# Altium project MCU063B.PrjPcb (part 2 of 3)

## Sheet MCU063B_Power.SchDoc
size 431 x 279 mm; Date: Not shown in title block; ApprovedBy: Not shown in title block; CheckedBy: Not shown in title block; Author: Not shown in title block; CompanyName: Not shown in title block; DrawnBy: Cody Watkins; Engineer: Not shown in title block; Organization: Not shown in title block; Address1: Not shown in title block; Address2: Not shown in title block; Address3: Not shown in title block; Address4: Not shown in title block; DocumentNumber: 5; Revision: Use project parameter SCH_Rev; SheetNumber: 5; SheetTotal: 11; PageSetup: Record=PageOptions¦CenterHorizontal=True¦CenterVertical=True¦PrintScale=1.00¦XCorrection=1.00¦YCorrection=1.00¦PrintKind=0¦BorderSize=5000000¦LeftOffset=0¦BottomOffset=0¦Orientation=2¦PaperLength=1000¦PaperWidth=1000¦Scale=100¦PaperSource=15¦PrintQuality=600¦MediaType=1¦DitherType=10¦PaperKind=Letter¦PrintScaleMode=1
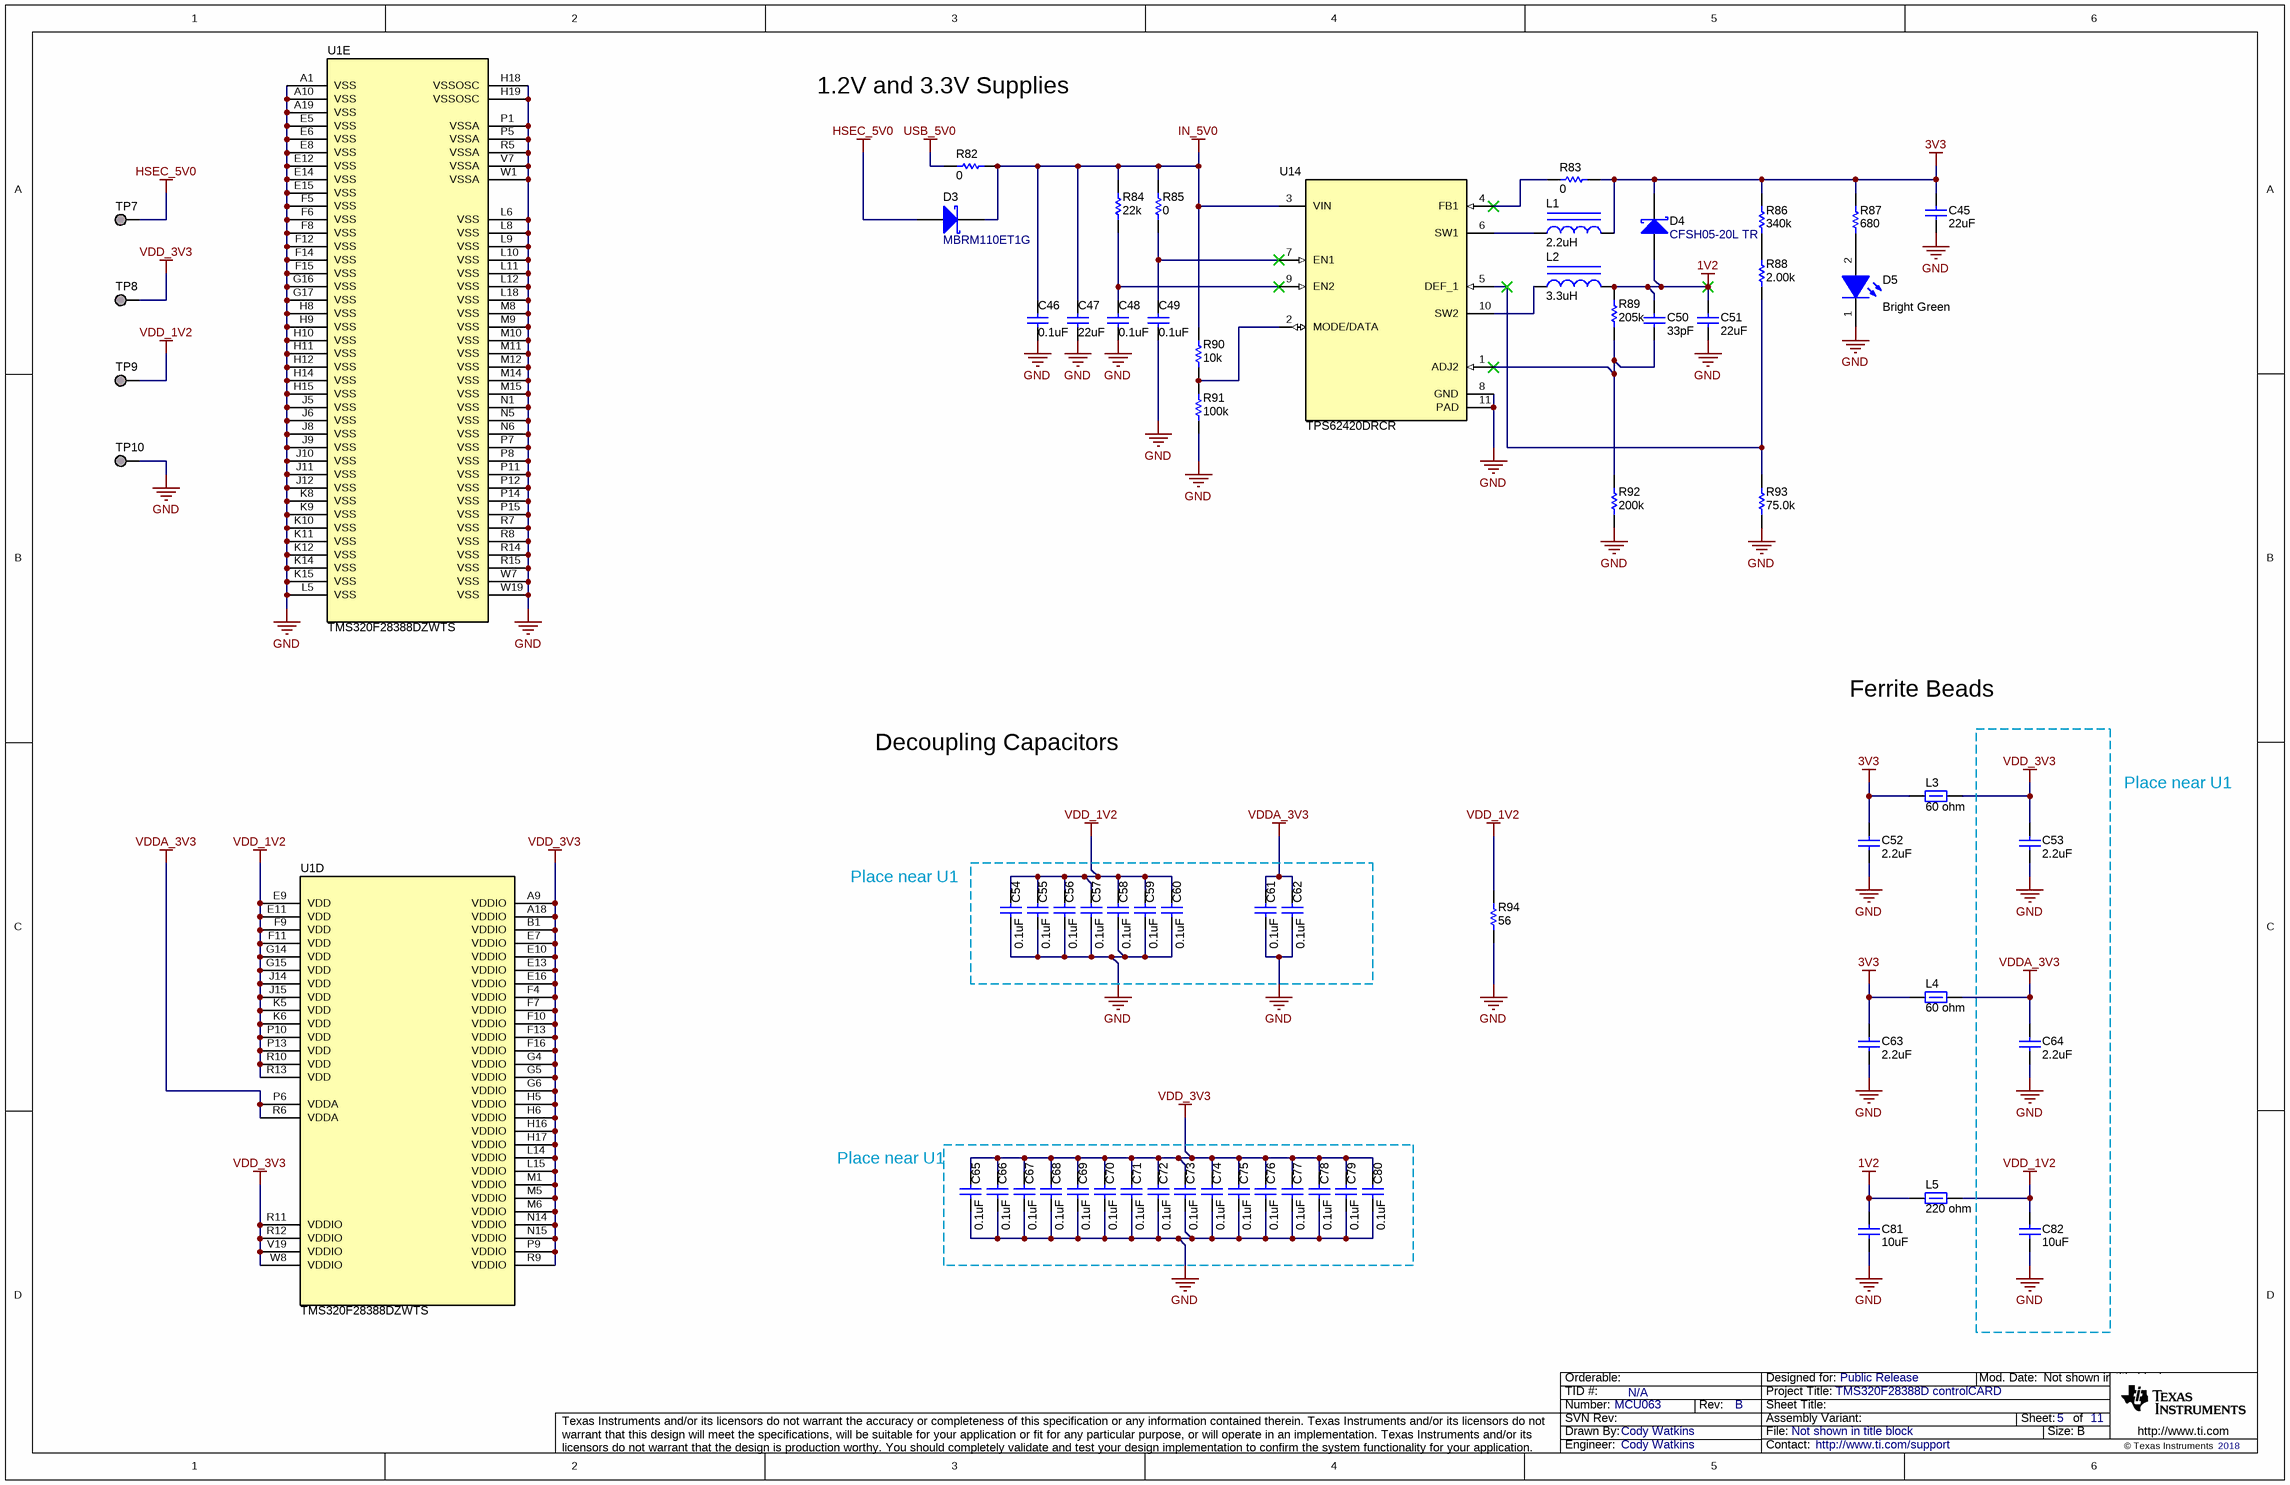
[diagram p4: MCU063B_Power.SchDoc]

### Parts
C45  ValueDisplayed: 22uF  [0805_HV]  (hidden comment: GRM21BR61C226ME44L)
C46  ValueDisplayed: 0.1uF  [0402]  (hidden comment: 0402YC104KAT2A)
C47  ValueDisplayed: 22uF  [0805_HV]  (hidden comment: GRM21BR61C226ME44L)
C48  ValueDisplayed: 0.1uF  [0402]  (hidden comment: 0402YC104KAT2A)
C49  ValueDisplayed: 0.1uF  [0402]  (hidden comment: 0402YC104KAT2A)
C50  ValueDisplayed: 33pF  [0402]  (hidden comment: 885012005043)
C51  ValueDisplayed: 22uF  [0805_HV]  (hidden comment: GRM21BR61C226ME44L)
C52  ValueDisplayed: 2.2uF  [0603]  (hidden comment: C0603C225K8PACTU)
C53  ValueDisplayed: 2.2uF  [0603]  (hidden comment: C0603C225K8PACTU)
C54  ValueDisplayed: 0.1uF  [0402]  (hidden comment: 0402YC104KAT2A)
C55  ValueDisplayed: 0.1uF  [0402]  (hidden comment: 0402YC104KAT2A)
C56  ValueDisplayed: 0.1uF  [0402L]  (hidden comment: 0402YC104KAT2A)
C57  ValueDisplayed: 0.1uF  [0402]  (hidden comment: 0402YC104KAT2A)
C58  ValueDisplayed: 0.1uF  [0402]  (hidden comment: 0402YC104KAT2A)
C59  ValueDisplayed: 0.1uF  [0402]  (hidden comment: 0402YC104KAT2A)
C60  ValueDisplayed: 0.1uF  [0402]  (hidden comment: 0402YC104KAT2A)
C61  ValueDisplayed: 0.1uF  [0402]  (hidden comment: 0402YC104KAT2A)
C62  ValueDisplayed: 0.1uF  [0402L]  (hidden comment: 0402YC104KAT2A)
C63  ValueDisplayed: 2.2uF  [0603]  (hidden comment: C0603C225K8PACTU)
C64  ValueDisplayed: 2.2uF  [0603]  (hidden comment: C0603C225K8PACTU)
C65  ValueDisplayed: 0.1uF  [0402]  (hidden comment: 0402YC104KAT2A)
C66  ValueDisplayed: 0.1uF  [0402]  (hidden comment: 0402YC104KAT2A)
C67  ValueDisplayed: 0.1uF  [0402]  (hidden comment: 0402YC104KAT2A)
C68  ValueDisplayed: 0.1uF  [0402]  (hidden comment: 0402YC104KAT2A)
C69  ValueDisplayed: 0.1uF  [0402]  (hidden comment: 0402YC104KAT2A)
C70  ValueDisplayed: 0.1uF  [0402]  (hidden comment: 0402YC104KAT2A)
C71  ValueDisplayed: 0.1uF  [0402]  (hidden comment: 0402YC104KAT2A)
C72  ValueDisplayed: 0.1uF  [0402]  (hidden comment: 0402YC104KAT2A)
C73  ValueDisplayed: 0.1uF  [0402]  (hidden comment: 0402YC104KAT2A)
C74  ValueDisplayed: 0.1uF  [0402]  (hidden comment: 0402YC104KAT2A)
C75  ValueDisplayed: 0.1uF  [0402]  (hidden comment: 0402YC104KAT2A)
C76  ValueDisplayed: 0.1uF  [0402]  (hidden comment: 0402YC104KAT2A)
C77  ValueDisplayed: 0.1uF  [0402]  (hidden comment: 0402YC104KAT2A)
C78  ValueDisplayed: 0.1uF  [0402]  (hidden comment: 0402YC104KAT2A)
C79  ValueDisplayed: 0.1uF  [0402]  (hidden comment: 0402YC104KAT2A)
C80  ValueDisplayed: 0.1uF  [0402]  (hidden comment: 0402YC104KAT2A)
C81  ValueDisplayed: 10uF  [0805_HV]  (hidden comment: C0805C106K8PACTU)
C82  ValueDisplayed: 10uF  [0603]  (hidden comment: GRM188R61A106ME69D)
D3  MBRM110ET1G  [POWERMITE]
D4  CFSH05-20L TR  [SOD-882L]
D5  value Bright Green  [WL-SMCW_Green_0805]  (hidden comment: 150080VS75000)
L1  ValueDisplayed: 2.2uH  [PFL3215]  (hidden comment: PFL3215-222MEB)
L2  ValueDisplayed: 3.3uH  [WE-MAIA_2510]  (hidden comment: 78438323033)
L3  value 60 ohm  [0805_HV]  (hidden comment: BKP2125HS600-T)
L4  value 60 ohm  [0805_HV]  (hidden comment: BKP2125HS600-T)
L5  value 220 ohm  [0805_HV]  (hidden comment: BLM21PG221SN1D)
R82  ValueDisplayed: 0  [0805_HV]  (hidden comment: MCR10EZPJ000)
R83  ValueDisplayed: 0  [0402]  (hidden comment: CRCW04020000Z0ED)
R84  ValueDisplayed: 22k  [0402]  (hidden comment: CRCW040222K0JNED)
R85  ValueDisplayed: 0  [0805_HV]  (hidden comment: MCR10EZPJ000)
R86  ValueDisplayed: 340k  [0402]  (hidden comment: CRCW0402340KFKED)
R87  ValueDisplayed: 680  [0402]  (hidden comment: CRCW0402680RJNED)
R88  ValueDisplayed: 2.00k  [0402]  (hidden comment: ERJ-2RKF2001X)
R89  ValueDisplayed: 205k  [0402]  (hidden comment: CRCW0402205KFKED)
R90  ValueDisplayed: 10k  [0402]  (hidden comment: CRCW040210K0JNED)
R91  ValueDisplayed: 100k  [0603]  (hidden comment: CRCW0603100KJNEA)
R92  ValueDisplayed: 200k  [0402]  (hidden comment: ERJ-2RKF2003X)
R93  ValueDisplayed: 75.0k  [0603]  (hidden comment: RT0603DRE0775KL)
R94  ValueDisplayed: 56  [0402]  (hidden comment: CRCW040256R0JNED)
TP7  TESTPOINT  [TP_50MIL-25MILHOLE]  (value not drawn)  (no BOM)
TP8  TESTPOINT  [TP_50MIL-25MILHOLE]  (value not drawn)  (no BOM)
TP9  TESTPOINT  [TP_50MIL-25MILHOLE]  (value not drawn)  (no BOM)
TP10  TESTPOINT  [TP_50MIL-25MILHOLE]  (value not drawn)  (no BOM)
U1  TMS320F28388DZWTS  [ZWT0337A]  (parts D,E of 5)
U14  TPS62420DRCR  [DRC0010J]

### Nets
1V2: C50.1 C51.1 C81.2 D4.2(A) L2.2 L5.1 R89.2
3V3: C45.1 C52.2 C63.2 D4.1(K) L1.2 L3.1 L4.1 R83.1 R86.2 R87.2
GND: C45.2 C46.2 C47.2 C48.2 C49.1 C51.2 C52.1 C53.1 C54.2 C55.2 C56.2 C57.2 C58.2 C59.2 C60.2 C61.2 C62.2 C63.1 C64.1 C65.2 C66.2 C67.2 C68.2 C69.2 C70.2 C71.2 C72.2 C73.2 C74.2 C75.2 C76.2 C77.2 C78.2 C79.2 C80.2 C81.1 C82.2 D5.1(K) R91.1 R92.1 R93.1 R94.1 TP10.1 U1.A1(VSS) U1.A10(VSS) U1.A19(VSS) U1.E5(VSS) U1.E6(VSS) U1.E8(VSS) U1.E12(VSS) U1.E14(VSS) U1.E15(VSS) U1.F5(VSS) U1.F6(VSS) U1.F8(VSS) U1.F12(VSS) U1.F14(VSS) U1.F15(VSS) U1.G16(VSS) U1.G17(VSS) U1.H8(VSS) U1.H9(VSS) U1.H10(VSS) U1.H11(VSS) U1.H12(VSS) U1.H14(VSS) U1.H15(VSS) U1.H18(VSSOSC) U1.H19(VSSOSC) U1.J5(VSS) U1.J6(VSS) U1.J8(VSS) U1.J9(VSS) U1.J10(VSS) U1.J11(VSS) U1.J12(VSS) U1.K8(VSS) U1.K9(VSS) U1.K10(VSS) U1.K11(VSS) U1.K12(VSS) U1.K14(VSS) U1.K15(VSS) U1.L5(VSS) U1.L6(VSS) U1.L8(VSS) U1.L9(VSS) U1.L10(VSS) U1.L11(VSS) U1.L12(VSS) U1.L18(VSS) U1.M8(VSS) U1.M9(VSS) U1.M10(VSS) U1.M11(VSS) U1.M12(VSS) U1.M14(VSS) U1.M15(VSS) U1.N1(VSS) U1.N5(VSS) U1.N6(VSS) U1.P1(VSSA) U1.P5(VSSA) U1.P7(VSS) U1.P8(VSS) U1.P11(VSS) U1.P12(VSS) U1.P14(VSS) U1.P15(VSS) U1.R5(VSSA) U1.R7(VSS) U1.R8(VSS) U1.R14(VSS) U1.R15(VSS) U1.V7(VSSA) U1.W1(VSSA) U1.W7(VSS) U1.W19(VSS) U14.8(GND) U14.11(PAD)
HSEC_5V0: D3.2(A) TP7.1
IN_5V0: C46.1 C47.1 D3.1(K) R82.1 R84.2 R85.1 R90.2 U14.3(VIN)
USB_5V0: R82.2
VDD_1V2: C54.1 C55.1 C56.1 C57.1 C58.1 C59.1 C60.1 C82.1 L5.2 R94.2 TP9.1 U1.E9(VDD) U1.E11(VDD) U1.F9(VDD) U1.F11(VDD) U1.G14(VDD) U1.G15(VDD) U1.J14(VDD) U1.J15(VDD) U1.K5(VDD) U1.K6(VDD) U1.P10(VDD) U1.P13(VDD) U1.R10(VDD) U1.R13(VDD)
VDD_3V3: C53.2 C65.1 C66.1 C67.1 C68.1 C69.1 C70.1 C71.1 C72.1 C73.1 C74.1 C75.1 C76.1 C77.1 C78.1 C79.1 C80.1 L3.2 TP8.1 U1.A9(VDDIO) U1.A18(VDDIO) U1.B1(VDDIO) U1.E7(VDDIO) U1.E10(VDDIO) U1.E13(VDDIO) U1.E16(VDDIO) U1.F4(VDDIO) U1.F7(VDDIO) U1.F10(VDDIO) U1.F13(VDDIO) U1.F16(VDDIO) U1.G4(VDDIO) U1.G5(VDDIO) U1.G6(VDDIO) U1.H5(VDDIO) U1.H6(VDDIO) U1.H16(VDDIO) U1.H17(VDDIO) U1.L14(VDDIO) U1.L15(VDDIO) U1.M1(VDDIO) U1.M5(VDDIO) U1.M6(VDDIO) U1.N14(VDDIO) U1.N15(VDDIO) U1.P9(VDDIO) U1.R9(VDDIO) U1.R11(VDDIO) U1.R12(VDDIO) U1.V19(VDDIO) U1.W8(VDDIO)
VDDA_3V3: C61.1 C62.1 C64.2 L4.2 U1.P6(VDDA) U1.R6(VDDA)
NetC48_1: C48.1 R84.1 U14.9(EN2)
NetC49_2: C49.2 R85.2 U14.7(EN1)
NetC50_2: C50.2 R89.1 R92.2 U14.1(ADJ2)
NetD5_2: D5.2(A) R87.1
NetL1_1: L1.1 U14.6(SW1)
NetL2_1: L2.1 U14.10(SW2)
NetR83_2: R83.2 U14.4(FB1)
NetR86_1: R86.1 R88.2
NetR88_1: R88.1 R93.2 U14.5(DEF_1)
NetR90_1: R90.1 R91.2 U14.2(MODE/DATA)

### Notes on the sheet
- 1.2V and 3.3V Supplies
- Ferrite Beads
- Decoupling Capacitors
- Place near U1
- (near C65) Place near U1

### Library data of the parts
C45 C47 C51 = CMP-0008294-2: CAP, CERM, 22 uF, 16 V, +/- 20%, X5R, 0805; Manufacturer: MuRata; TaMin_C: -55°C; Polarized: N; SizeAreaWB_mm2: 6.75; Value1: Unknown; U/M: EA; Value: 22uF; TaMax_C: 85°C; SizeZ_mm: 1.45; SizeX_mm: 2; SizeY_mm: 1.25; Cap_Case: 0805; Value2: 16V; SizeArea_mm2: 2.5; Cap_F: 22µF; AEC Category: Q200
C46 C48 C49 C54 C55 C57-C61 C65-C80 = CMP-0006201-2: CAP, CERM, 0.1 uF, 16 V, +/- 10%, X7R, 0402; Manufacturer: AVX; TaMin_C: -55°C; Polarized: N; SizeAreaWB_mm2: 3; Value1: Unknown; U/M: EA; Value: 0.1uF; TaMax_C: 125°C; SizeZ_mm: 0.6; SizeX_mm: 1; SizeY_mm: 0.5; Value2: 16V; Cap_F: 100nF; AEC Category: Q200
C50 = CMP-0006213-2: CAP, CERM, 33 pF, 25 V, +/- 5%, C0G/NP0, 0402; Manufacturer: Wurth Elektronik; TaMin_C: -55°C; Polarized: N; SizeAreaWB_mm2: 3; Value1: Unknown; U/M: EA; Value: 33pF; TaMax_C: 125°C; SizeZ_mm: 0.6; SizeX_mm: 1; SizeY_mm: 0.5; Value2: 25V; AEC Category: Q200
C52 C53 C63 C64 = CMP-0006906-5: CAP, CERM, 2.2 uF, 10 V, +/- 10%, X5R, 0603; Manufacturer: Kemet; TaMin_C: -55°C; Polarized: N; SizeAreaWB_mm2: 4.68; Value1: Unknown; U/M: EA; Value: 2.2uF; TaMax_C: 85°C; SizeZ_mm: 1; SizeX_mm: 1.6; SizeY_mm: 0.8; Value2: 10V; SizeArea_mm2: 1.28; Cap_F: 2.2µF; AEC Category: Q200
C56 C62 = CMP-0006201-2: CAP, CERM, 0.1 uF, 16 V, +/- 10%, X7R, 0402; Manufacturer: AVX; TaMin_C: -55°C; Polarized: N; SizeAreaWB_mm2: 3; Value1: Unknown; U/M: EA; Value: 0.1uF; TaMax_C: 125°C; SizeZ_mm: 0.6; SizeX_mm: 1; SizeY_mm: 0.5; Cap_Case: 0402; Value2: 16V; Cap_F: 100nF; AEC Category: Q200
C81 = CMP-0007732-2: CAP, CERM, 10 uF, 10 V, +/- 10%, X5R, 0805; Manufacturer: Kemet; TaMin_C: -55°C; ESR_ohm: 3m; Polarized: N; SizeAreaWB_mm2: 6.75; Value1: 0.003 ohm; U/M: EA; Value: 10uF; TaMax_C: 85°C; SizeZ_mm: 1.45; SizeX_mm: 2; SizeY_mm: 1.25; Cap_Case: 0805; Value2: 10V; SizeArea_mm2: 2.5; Cap_F: 10µF; IRMS_A: 11.43A; AEC Category: Q200
C82 = CMP-0007318-5: CAP, CERM, 10 uF, 10 V, +/- 20%, X5R, 0603; Manufacturer: MuRata; Polarized: N; Value: 10uF; U/M: EA; Cap_F: 10µF; Value1: Unknown; VDC_V: 10V; TaMin_C: -55°C; TaMax_C: 85°C; AEC Category: Q200; SizeArea_mm2: 1.28; SizeAreaWB_mm2: 4.68; SizeX_mm: 1.6; SizeY_mm: 0.8; SizeZ_mm: 1
D3 = CMP-0028747-2: Diode, Schottky, 10 V, 1 A, AEC-Q101, POWERMITE; Manufacturer: ON Semiconductor; Vf_V: 530mV; Value: 10V; Green_REACh: Incomplete; Io_A: 1A; SizeZ_mm: 1.15; AEC Category: Q101; SizeX_mm: 3.9; AEC Qualified: Y; Value2: 0.53V; SizeAreaWB_mm2: 14.945; SizeArea_mm2: 7.995; TJmax_C: 150°C; Green_Lifecycle: Not Set; SizeY_mm: 2.05
D4 = CMP-0028751-2: Diode, Schottky, 20 V, 0.5 A, 1.0x0.35x0.6mm; Manufacturer: Central Semiconductor; Io_A: 500mA; Green_Lifecycle: Not Set; SizeAreaWB_mm2: 3.2; Vr_V: 20V; Green_REACh: Incomplete; Value1: 0.5A; TJmax_C: 150°C; Value: 20V; SizeZ_mm: 0.4; SizeX_mm: 1; SizeY_mm: 0.6; Vf_V: 500mV; Value2: 0.5V; AEC Qualified: N; AEC Category: Q101
D5 = CMP-0002960-2: LED, Bright Green, SMD; Manufacturer: Wurth Elektronik; Type: AlInGaP; Vf_V: 2V; Io_A: 20mA; Vr_V: 5V; Tjmax_C: 85°C; Power_TotalModule: 72mW; Value1: 0.072W; Angle: 140; U/M: EA
L1 = CMP-0060725-1: Inductor, Shielded, Composite, 2.2 uH, 1.1 A, 0.114 ohm, SMD; Manufacturer: Coilcraft; Isat: 1.2A @ 20% inductance drop; Irms: 1.1A @ 20C rise; Green_Lifecycle: Not Set; SizeAreaWB_mm2: 13.8012; DCR_ohm: 1.14d; Green_REACh: Incomplete; Value: 2.2uH; Imax_A: 1.1A; SizeZ_mm: 1.5; SizeX_mm: 3.2; SizeY_mm: 2.286; SizeArea_mm2: 7.3152; Ind_H: 2.2µH; AEC Category: Q200
L2 = CMP-0064350-1: Inductor, Shielded, Powdered Iron, 3.3 uH, 1.25 A, 0.264 ohm, AEC-Q200 Grade 1, SMD; Manufacturer: Wurth Elektronik; Isat: 2.1A @ 20% inductance drop; Irms: 1.25A @ 40C rise; SizeAreaWB_mm2: 10.5; DCR_ohm: 2.64d; Value: 3.3uH; Imax_A: 1.25A; SizeZ_mm: 1; SizeX_mm: 2.5; SizeY_mm: 2; SizeArea_mm2: 5; Ind_H: 3.3µH; AEC Qualified: Y; AEC Category: Q200
L3 L4 = CMP-0003306-1: Ferrite Bead, 60 ohm @ 100 MHz, 3 A, 0805; Manufacturer: Taiyo Yuden; Imax_A: 3A; DCR_ohm: 0.025; Value1: 0.025 ohm; ZTyp@100MHz_Ohm: 60; SizeArea_mm2: 2.5; SizeAreaWB_mm2: 6.75; SizeX_mm: 2; SizeY_mm: 1.25; SizeZ_mm: 1.45
L5 = CMP-0003363-1: Ferrite Bead, 220 ohm @ 100 MHz, 2 A, 0805; Manufacturer: MuRata; Imax_A: 2A; DCR_ohm: 0.045; Value1: 0.045 ohm; ZTyp@100MHz_Ohm: 220; SizeArea_mm2: 2.5; SizeAreaWB_mm2: 6.75; SizeX_mm: 2; SizeY_mm: 1.25; SizeZ_mm: 1.45
R82 R85 = CMP-0020802-2: RES, 0, 5%, 0.125 W, 0805; Manufacturer: Rohm; Power_W: 125mW; TempCo: 400 ppm/C; Value_Code: 0000; U/M: EA; Value: 0; EIA_Code: E24; SizeX_mm: 2; SizeY_mm: 1.25; SizeZ_mm: 1.45; Value2: 0.125W; SizeArea_mm2: 2.5; VDC_V: 150V; AEC Category: Q200
R83 = CMP-0026822-3: RES, 0, 5%, 0.063 W, AEC-Q200 Grade 0, 0402; Manufacturer: Vishay-Dale; Power_W: 63mW; TempCo: 200 ppm/C; Value_Code: 0000; Value: 0; EIA_Code: E24; SizeX_mm: 1; SizeY_mm: 0.5; SizeZ_mm: 0.6; Value2: 0.063W; AEC Qualified: Y; VDC_V: 50V; AEC Category: Q200
R84 = CMP-0026879-3: RES, 22 k, 5%, 0.063 W, AEC-Q200 Grade 0, 0402; Manufacturer: Vishay-Dale; Power_W: 63mW; TempCo: 200 ppm/C; Value_Code: 22k0; Value: 22k; EIA_Code: E24; SizeX_mm: 1; SizeY_mm: 0.5; SizeZ_mm: 0.6; Value2: 0.063W; AEC Qualified: Y; VDC_V: 50V; AEC Category: Q200; AEC Grade: 0
R86 = CMP-0026300-2: RES, 340 k, 1%, 0.063 W, AEC-Q200 Grade 0, 0402; Manufacturer: Vishay-Dale; Power_W: 63mW; TempCo: 100 ppm/C; Value: 340k; EIA_Code: E96; SizeX_mm: 1; SizeY_mm: 0.5; SizeZ_mm: 0.6; Value2: 0.063W; AEC Qualified: Y; VDC_V: 50V; AEC Category: Q200; AEC Grade: 0
R87 = CMP-0026962-3: RES, 680, 5%, 0.063 W, AEC-Q200 Grade 0, 0402; Manufacturer: Vishay-Dale; Power_W: 63mW; TempCo: 200 ppm/C; Value_Code: 680R; Value: 680; EIA_Code: E24; SizeX_mm: 1; SizeY_mm: 0.5; SizeZ_mm: 0.6; Value2: 0.063W; AEC Qualified: Y; VDC_V: 50V; AEC Category: Q200; AEC Grade: 0
R88 = CMP-0026676-1: RES, 2.00 k, 1%, 0.1 W, AEC-Q200 Grade 0, 0402; Manufacturer: Panasonic; Power_W: 100mW; TempCo: 100 ppm/C; Value_Code: 2k00; U/M: EA; Value: 2.00k; EIA_Code: E96; Res_ohm: 2k; SizeX_mm: 1; SizeY_mm: 0.5; SizeZ_mm: 0.6; Value2: 0.1W; AEC Qualified: Y; VDC_V: 50V; AEC Grade: 0; AEC Category: Q200
R89 = CMP-0026160-2: RES, 205 k, 1%, 0.063 W, AEC-Q200 Grade 0, 0402; Manufacturer: Vishay-Dale; Power_W: 63mW; TempCo: 100 ppm/C; Value: 205k; EIA_Code: E96; SizeX_mm: 1; SizeY_mm: 0.5; SizeZ_mm: 0.6; Value2: 0.063W; AEC Qualified: Y; VDC_V: 50V; AEC Category: Q200; AEC Grade: 0
R90 = CMP-0026825-5: RES, 10 k, 5%, 0.063 W, AEC-Q200 Grade 0, 0402; Manufacturer: Vishay-Dale; Power_W: 63mW; TempCo: 200 ppm/C; Value_Code: 10k0; Value: 10k; EIA_Code: E24; SizeX_mm: 1; SizeY_mm: 0.5; SizeZ_mm: 0.6; Value2: 0.063W; AEC Qualified: Y; VDC_V: 50V; AEC Category: Q200; AEC Grade: 0
R91 = CMP-0025698-4: RES, 100 k, 5%, 0.1 W, AEC-Q200 Grade 0, 0603; Manufacturer: Vishay-Dale; Power_W: 100mW; TempCo: 200 ppm/C; Value: 100k; EIA_Code: E24; SizeX_mm: 1.6; SizeY_mm: 0.8; SizeZ_mm: 1; Value2: 0.1W; SizeArea_mm2: 1.28; AEC Qualified: Y; VDC_V: 75V; AEC Category: Q200; AEC Grade: 0
R92 = CMP-0026677-1: RES, 200 k, 1%, 0.1 W, 0402; Manufacturer: Panasonic; Power_W: 100mW; TempCo: 100 ppm/C; U/M: EA; Value: 200k; EIA_Code: E96; SizeX_mm: 1; SizeY_mm: 0.5; SizeZ_mm: 0.6; Value2: 0.1W; VDC_V: 50V; AEC Category: Q200
R93 = CMP-0025557-3: RES, 75.0 k, 0.5%, 0.1 W, 0603; Manufacturer: Yageo America; Power_W: 100mW; TempCo: 50 ppm/C; Value_Code: 75k0; U/M: EA; Value: 75.0k; EIA_Code: E192; Res_ohm: 75k; SizeX_mm: 1.6; SizeY_mm: 0.8; SizeZ_mm: 1; Value2: 0.1W; SizeArea_mm2: 1.28; VDC_V: 75V; AEC Category: Q200
R94 = CMP-0026950-3: RES, 56, 5%, 0.063 W, AEC-Q200 Grade 0, 0402; Manufacturer: Vishay-Dale; Power_W: 63mW; TempCo: 200 ppm/C; Value_Code: 56R0; Value: 56; EIA_Code: E24; SizeX_mm: 1; SizeY_mm: 0.5; SizeZ_mm: 0.6; Value2: 0.063W; AEC Qualified: Y; VDC_V: 50V; AEC Category: Q200; AEC Grade: 0
TP7-TP10 = CMP-0078143-3: TEST POINT.  No entry in BOM.
U1 = CMP-0081777-3: TMS320F28388DZWTS, ZWT0337A (NFBGA-337); Manufacturer: Texas Instruments; SizeAreaWB_mm2: 324; SizeArea_mm2: 256; AEC Qualified: N; AEC Category: Q200; SizeZ_mm: 1.4; SizeY_mm: 16; CompType: IC
U14 = CMP-0037884-5: Dual, Adjustable, 600mA and 1000mA, 2.25MHz Step-Down Converter with 1-Wire Interface in QFN, DRC0010J (VSON-10); Manufacturer: Texas Instruments; Vin(Min)(V): 2.5; Regulated Outputs(#): 2; SizeY_mm: 3; Iout2(Max)(A): 1; Duty Cycle(Max)(%): 100; AEC Qualified: N; Dynamic Voltage Scaling: TRUE; Vout(Min)(V): 0.6; Vin(Max)(V): 6; Topology: Buck; SizeAreaWB_mm2: 16; CompType: IC; SizeArea_mm2: 9; Rating: Catalog; Iq(Typ)(mA): 0.032; AEC Category: Q200

## Sheet MCU063B_USB.SchDoc
size 431 x 279 mm; Date: Not shown in title block; ApprovedBy: Not shown in title block; CheckedBy: Not shown in title block; Author: Not shown in title block; CompanyName: Not shown in title block; DrawnBy: Cody Watkins; Engineer: Not shown in title block; Organization: Not shown in title block; Address1: Not shown in title block; Address2: Not shown in title block; Address3: Not shown in title block; Address4: Not shown in title block; DocumentNumber: 6; Revision: Use project parameter SCH_Rev; SheetNumber: 6; SheetTotal: 11; PageSetup: Record=PageOptions¦CenterHorizontal=True¦CenterVertical=True¦PrintScale=1.00¦XCorrection=1.00¦YCorrection=1.00¦PrintKind=0¦BorderSize=5000000¦LeftOffset=0¦BottomOffset=0¦Orientation=2¦PaperLength=1000¦PaperWidth=1000¦Scale=100¦PaperSource=15¦PrintQuality=600¦MediaType=1¦DitherType=10¦PaperKind=Letter¦PrintScaleMode=1
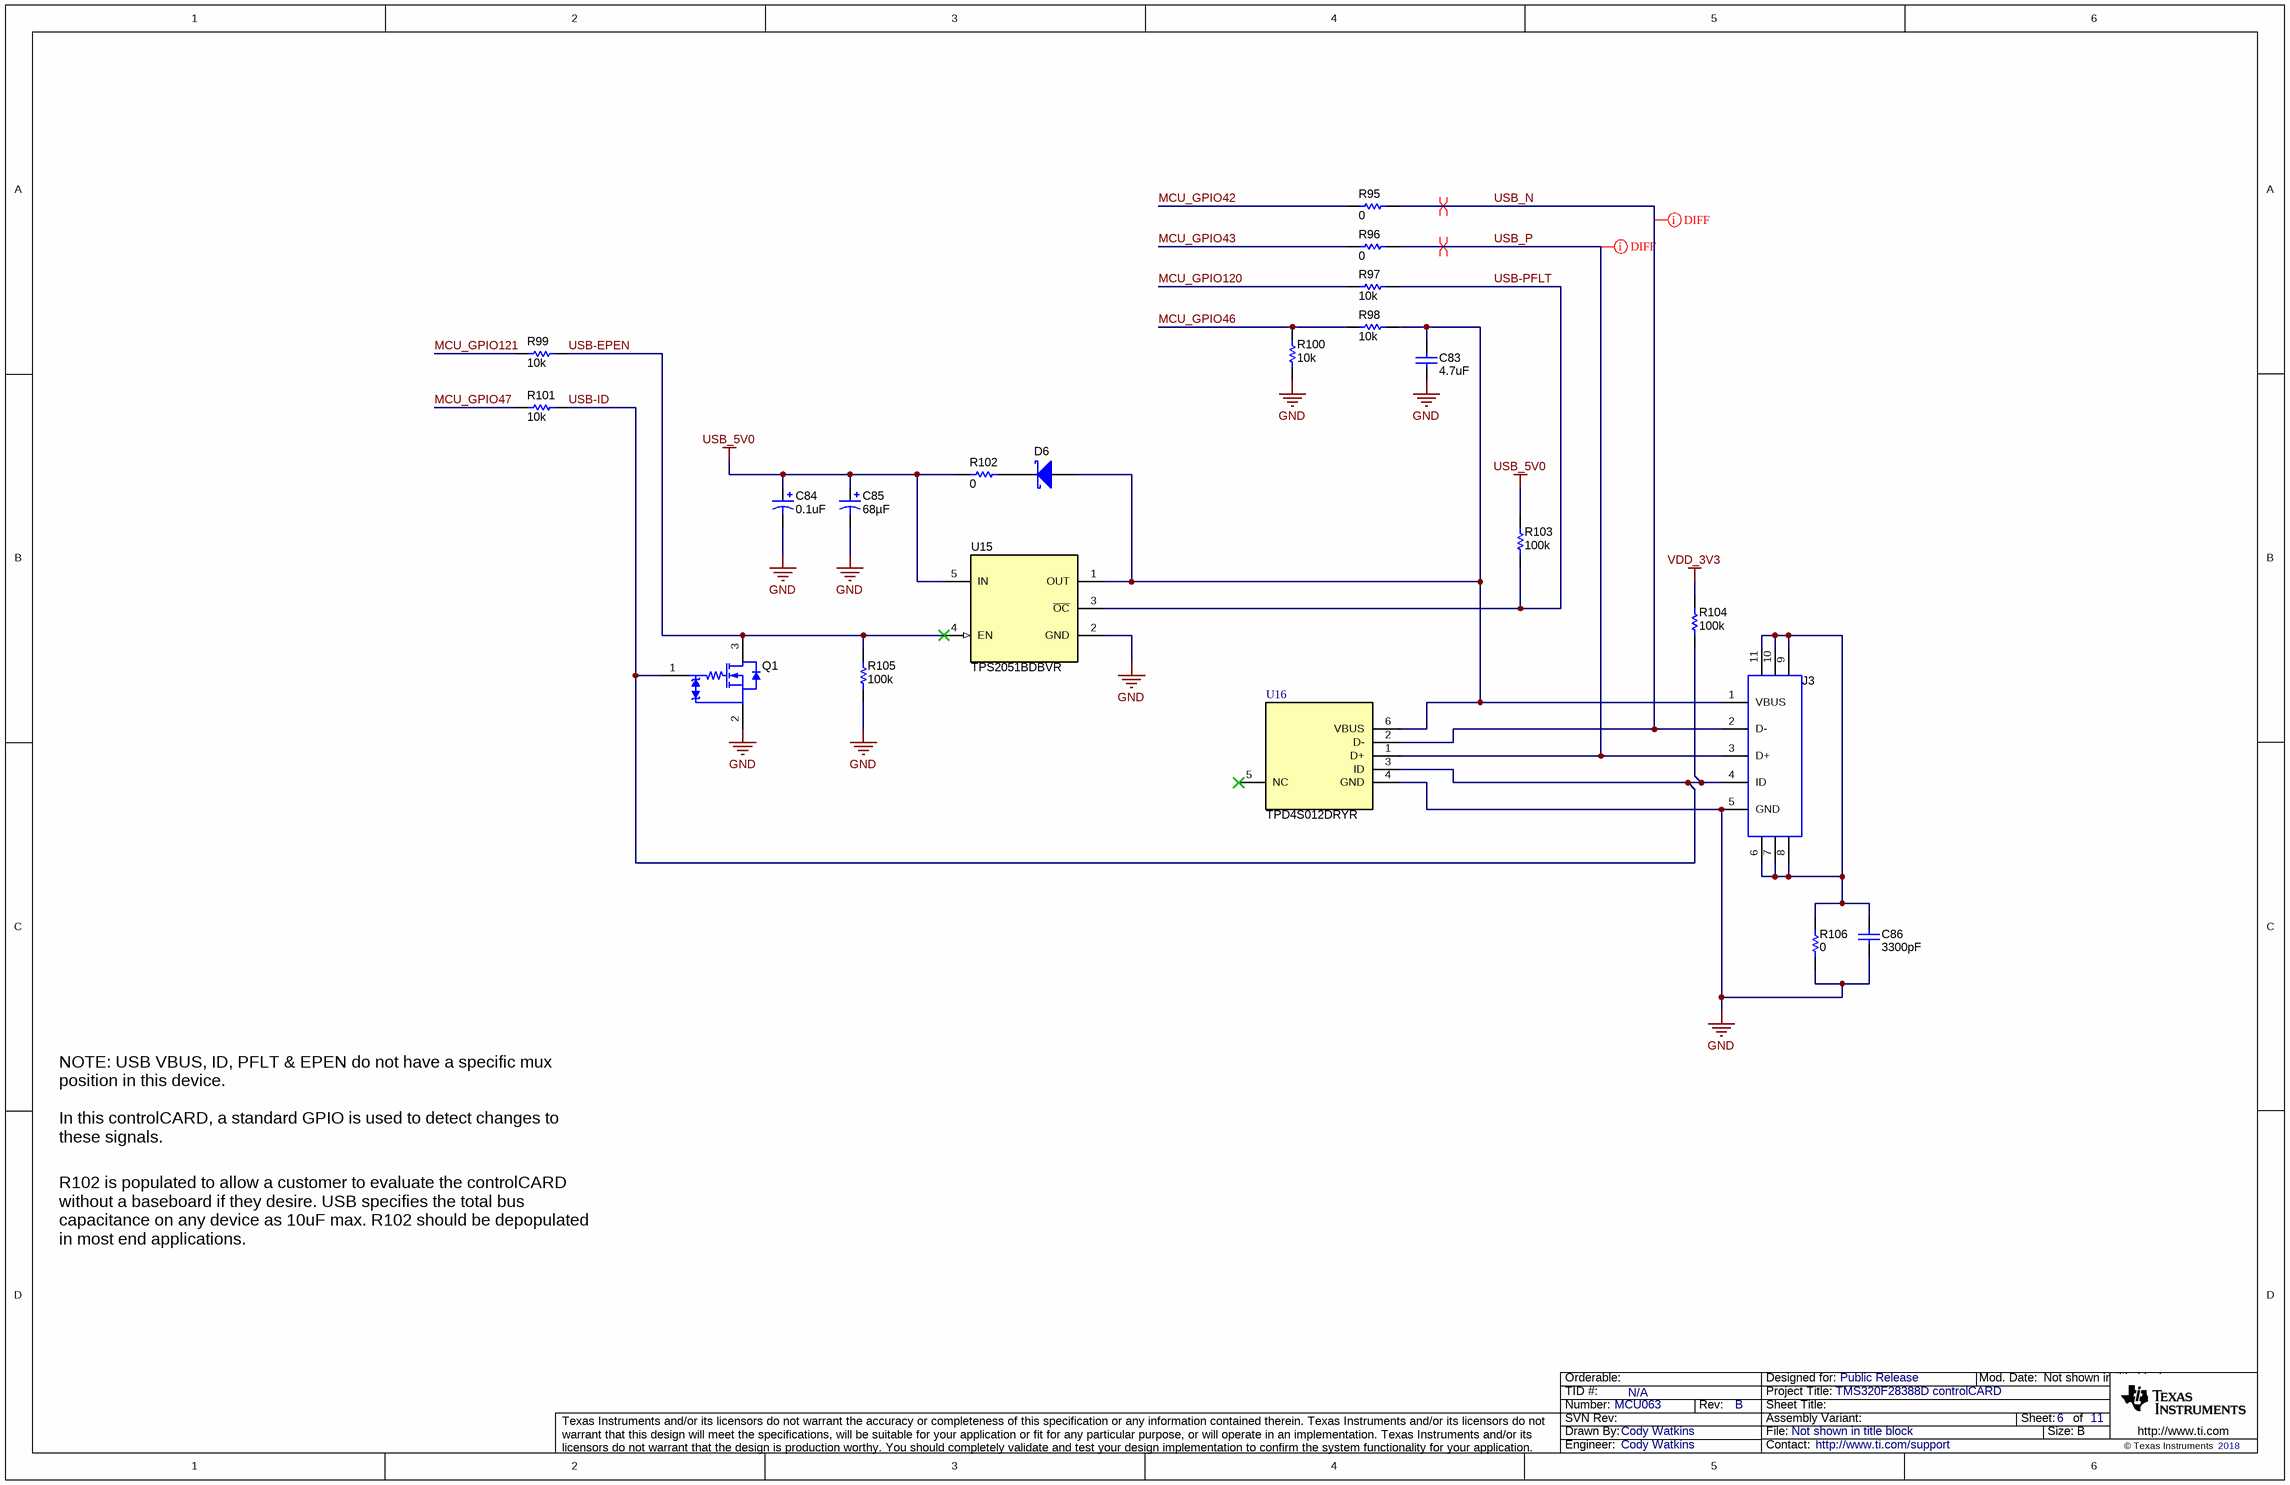
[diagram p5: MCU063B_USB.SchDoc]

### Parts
C83  ValueDisplayed: 4.7uF  [0603]  (hidden comment: C0603C475K9PACTU)
C84  ValueDisplayed: 0.1uF  [3216-18]  (hidden comment: 293D104X9035A2TE3)
C85  ValueDisplayed: 68µF  [3216-18]  (hidden comment: TLJA686M010R1500)
C86  ValueDisplayed: 3300pF  [0402]  (hidden comment: CGA2B2X7R1H332K050BA)
D6  MBRM110ET1G  [POWERMITE]  (value not drawn)
J3  1051640001  [Molex_1051640001]  (value not drawn)
Q1  NTA7002NT1G  [SOT-416]  (value not drawn)
R95  ValueDisplayed: 0  [0402]  (hidden comment: CRCW04020000Z0ED)
R96  ValueDisplayed: 0  [0402]  (hidden comment: CRCW04020000Z0ED)
R97  ValueDisplayed: 10k  [0805_HV]  (hidden comment: ERJ-6GEYJ103V)
R98  ValueDisplayed: 10k  [0805_HV]  (hidden comment: ERJ-6GEYJ103V)
R99  ValueDisplayed: 10k  [0805_HV]  (hidden comment: ERJ-6GEYJ103V)
R100  ValueDisplayed: 10k  [0805_HV]  (hidden comment: ERJ-6GEYJ103V)
R101  ValueDisplayed: 10k  [0805_HV]  (hidden comment: ERJ-6GEYJ103V)
R102  ValueDisplayed: 0  [0402]  (hidden comment: CRCW04020000Z0ED)
R103  ValueDisplayed: 100k  [0603]  (hidden comment: ERJ-3GEYJ104V)
R104  ValueDisplayed: 100k  [0603]  (hidden comment: ERJ-3GEYJ104V)
R105  ValueDisplayed: 100k  [0603]  (hidden comment: ERJ-3GEYJ104V)
R106  ValueDisplayed: 0  [0402]  (hidden comment: CRCW04020000Z0ED)
U15  TPS2051BDBVR  [DBV0005A_N]
U16  TPD4S012DRYR  [DRY0006A]

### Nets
GND: C83.2 C84.2(-) C85.2(-) C86.1 J3.5(GND) Q1.2(S) R100.1 R105.2 R106.2 U15.2(GND) U16.4(GND)
USB_5V0: C84.1(+) C85.1(+) R102.1 R103.1 U15.5(IN)
VDD_3V3: R104.1
MCU_GPIO42: R95.1
MCU_GPIO43: R96.1
MCU_GPIO46: R98.1 R100.2
MCU_GPIO47: R101.1
MCU_GPIO120: R97.1
MCU_GPIO121: R99.1
USB-EPEN: Q1.3(D) R99.2 R105.1 U15.4(EN)
USB-ID: J3.4(ID) Q1.1(G) R101.2 R104.2 U16.3(ID)
USB-PFLT: R97.2 R103.2 U15.3(~{OC})
USB_N: J3.2(D-) R95.2 U16.2(D-)
USB_P: J3.3(D+) R96.2 U16.1(D+)
NetC83_1: C83.1 D6.2(A) J3.1(VBUS) R98.2 U15.1(OUT) U16.6(VBUS)
NetC86_2: C86.2 J3.6 J3.7 J3.8 J3.9 J3.10 J3.11 R106.1
NetD6_1: D6.1(K) R102.2

Not connected (* = marked no-connect by the designer): U16 5(NC)*

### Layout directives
differential pair: USB_N, USB_P
net class USB: USB_N, USB_P

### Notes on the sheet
- NOTE: USB VBUS, ID, PFLT & EPEN do not have a specific mux position in this device.
  In this controlCARD, a standard GPIO is used to detect changes to these signals.
- R102 is populated to allow a customer to evaluate the controlCARD without a baseboard if they desire. USB specifies the total bus capacitance on any device as 10uF max. R102 should be depopulated in most end applications.

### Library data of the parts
C83 = CMP-0006950-5: CAP, CERM, 4.7 uF, 6.3 V, +/- 10%, X5R, 0603; Manufacturer: Kemet; TaMin_C: -55°C; ESR_ohm: 6m; Polarized: N; SizeAreaWB_mm2: 4.68; Value1: 0.006 ohm; U/M: EA; Value: 4.7uF; TaMax_C: 85°C; SizeZ_mm: 1; SizeX_mm: 1.6; SizeY_mm: 0.8; Value2: 6.3V; SizeArea_mm2: 1.28; Cap_F: 4.7µF; IRMS_A: 7.24A; AEC Category: Q200
C84 = CMP-0011440-2: CAP, TA, 0.1 uF, 35 V, +/- 10%, 20 ohm, SMD; Manufacturer: Vishay-Sprague; TaMin_C: -55°C; ESR_ohm: 20; Polarized: Y; SizeAreaWB_mm2: 10.92; Value1: 20 ohm; U/M: EA; Value: 0.1uF; TaMax_C: 125°C; SizeZ_mm: 1.8; SizeX_mm: 3.2; SizeY_mm: 1.6; Cap_Case: A; Value2: 35V; SizeArea_mm2: 5.12; CompType: Capacitor; Cap_F: 100nF; IRMS_A: 60mA; AEC Category: Q200
C85 = CMP-0081926-1: CAP, TA, 68 µF, 10 V, +/- 20%, 1.5 ohm, SMD; Manufacturer: AVX; TaMin_C: -55°C; ESR_ohm: 1.5; Polarized: Y; SizeAreaWB_mm2: 10.92; Value1: 1.5 ohm; Value: 68uF; TaMax_C: 125°C; SizeZ_mm: 1.8; SizeX_mm: 3.2; SizeY_mm: 1.6; Value2: 10V; SizeArea_mm2: 5.12; CompType: Capacitor; AEC Qualified: N; IRMS_A: 2.24dA; AEC Category: Q200
C86 = CMP-0006319-2: CAP, CERM, 3300 pF, 50 V, +/- 10%, X7R, AEC-Q200 Grade 1, 0402; Manufacturer: TDK; TaMin_C: -55°C; ESR_ohm: 7.85178d; Polarized: N; SizeAreaWB_mm2: 3; Value1: 0.785178 ohm; U/M: EA; Value: 3300pF; TaMax_C: 125°C; SizeZ_mm: 0.6; SizeX_mm: 1; SizeY_mm: 0.5; Value2: 50V; AEC Qualified: Y; Cap_F: 3.3nF; IRMS_A: 2.72902dA; AEC Category: Q200
D6 = CMP-0028747-2: Diode, Schottky, 10 V, 1 A, AEC-Q101, POWERMITE; Manufacturer: ON Semiconductor; Io_A: 1A; Green_Lifecycle: Not Set; SizeAreaWB_mm2: 14.945; Vr_V: 10V; Green_REACh: Incomplete; TJmax_C: 150°C; Value: 10V; SizeZ_mm: 1.15; SizeX_mm: 3.9; SizeY_mm: 2.05; Vf_V: 530mV; Value2: 0.53V; SizeArea_mm2: 7.995; AEC Qualified: Y; AEC Category: Q101
J3 = CMP-0055311-1: Receptacle, USB 2.0, Micro B, 5 Position, R/A, SMT; Manufacturer: Molex; CNHeader: FALSE; Current_A: 1.8A; Gender: Female; Voltage_V: 30V; Pitch_mm: 0.65; ContactFinish: Gold; CT: TRUE; Cert_UL: Y
Q1 = CMP-0081965-1: MOSFET, N-CH, 30 V, 0.154 A, AEC-Q101, SOT-416; Manufacturer: ON Semiconductor; Alternate Manufacturer: None; ChType: N; SizeAreaWB_mm2: 6.76; SizeArea_mm2: 2.56; IdsMax_A: 1.54dA; AEC Qualified: Y; VdsMax_V: 30V; Rdson45_ohm: 7; Vgs_V: 10V; AEC Category: Q101; Value: 30V; SizeZ_mm: 0.95; ChMode: Enhancement; SizeY_mm: 1.6; Value2: ? nC; Value1: 7 ohm
R95 R96 R102 = CMP-0026822-3: RES, 0, 5%, 0.063 W, AEC-Q200 Grade 0, 0402; Manufacturer: Vishay-Dale; Value: 0; Value_Code: 0000; Power_W: 63mW; Value2: 0.063W; VDC_V: 50V; TempCo: 200 ppm/C; SizeArea_mm2: 0.5; SizeX_mm: 1; SizeZ_mm: 0.6; EIA_Code: E24; AEC Category: Q200; AEC Qualified: Y
R97-R101 = CMP-0020620-3: RES, 10 k, 5%, 0.125 W, AEC-Q200 Grade 0, 0805; Manufacturer: Panasonic; Power_W: 125mW; TempCo: 200 ppm/C; Value_Code: 10k0; Value: 10k; EIA_Code: E24; SizeX_mm: 2; SizeY_mm: 1.25; SizeZ_mm: 1.45; Value2: 0.125W; SizeArea_mm2: 2.5; AEC Qualified: Y; VDC_V: 150V; AEC Category: Q200; AEC Grade: 0; SizeAreaWB_mm2: 6.75
R103-R105 = CMP-0025875-3: RES, 100 k, 5%, 0.1 W, AEC-Q200 Grade 0, 0603; Manufacturer: Panasonic; Power_W: 100mW; TempCo: 200 ppm/C; U/M: EA; Value: 100k; EIA_Code: E24; SizeX_mm: 1.6; SizeY_mm: 0.8; SizeZ_mm: 1; Value2: 0.1W; SizeArea_mm2: 1.28; AEC Qualified: Y; VDC_V: 50V; AEC Grade: 0; AEC Category: Q200
R106 = CMP-0026822-3: RES, 0, 5%, 0.063 W, AEC-Q200 Grade 0, 0402; Manufacturer: Vishay-Dale; Value: 0; Value_Code: 0000; Power_W: 63mW; Value2: 0.063W; VDC_V: 50V; TempCo: 200 ppm/C; EIA_Code: E24; AEC Category: Q200; AEC Qualified: Y; SizeArea_mm2: 0.5; SizeX_mm: 1; SizeZ_mm: 0.6
U15 = CMP-0074276-1: Single, Current-Limited, Power-Distribution Switch, DBV0005A (SOT-23-5); Alternate PartNumber: TPS2051BDBVT; Alternate Manufacturer: Texas Instruments; Green_Lifecycle: Active; SizeAreaWB_mm2: 14.82; Green_REACh: Passed; U/M: EA; SizeZ_mm: 1.45; SizeX_mm: 2.8; SizeY_mm: 2.9; SizeArea_mm2: 8.12; CompType: IC
U16 = CMP-0043122-3: 4-Channel USB ESD Solution with Power Clamp, DRY0006A (USON-6); Manufacturer: Texas Instruments; IO Leakage Current(nA): 10; USB High Speed: TRUE; Eco-Plan: Green (RoHS & no Sb/Br); Breakdown Voltage(Min)(V): 6; IO Capacitance(Typ)(pF): 0.8; AEC Category: Q200; AEC Qualified: N; CompType: IC; SizeAreaWB_mm2: 4.9; SizeArea_mm2: 1.45; SizeX_mm: 1.0; SizeZ_mm: 0.6; Rating: Catalog

## Sheet MCU063B_EtherNET.SchDoc
size 431 x 279 mm; Date: Not shown in title block; ApprovedBy: Not shown in title block; CheckedBy: Not shown in title block; Author: Not shown in title block; CompanyName: Not shown in title block; Engineer: Not shown in title block; Organization: Not shown in title block; Address1: Not shown in title block; Address2: Not shown in title block; Address3: Not shown in title block; Address4: Not shown in title block; DocumentNumber: 7; Revision: Use project parameter SCH_Rev; SheetNumber: 7; SheetTotal: 11; PageSetup: Record=PageOptions¦CenterHorizontal=True¦CenterVertical=True¦PrintScale=1.00¦XCorrection=1.00¦YCorrection=1.00¦PrintKind=0¦BorderSize=5000000¦LeftOffset=0¦BottomOffset=0¦Orientation=2¦PaperLength=1000¦PaperWidth=1000¦Scale=100¦PaperSource=15¦PrintQuality=600¦MediaType=1¦DitherType=10¦PaperKind=Letter¦PrintScaleMode=1
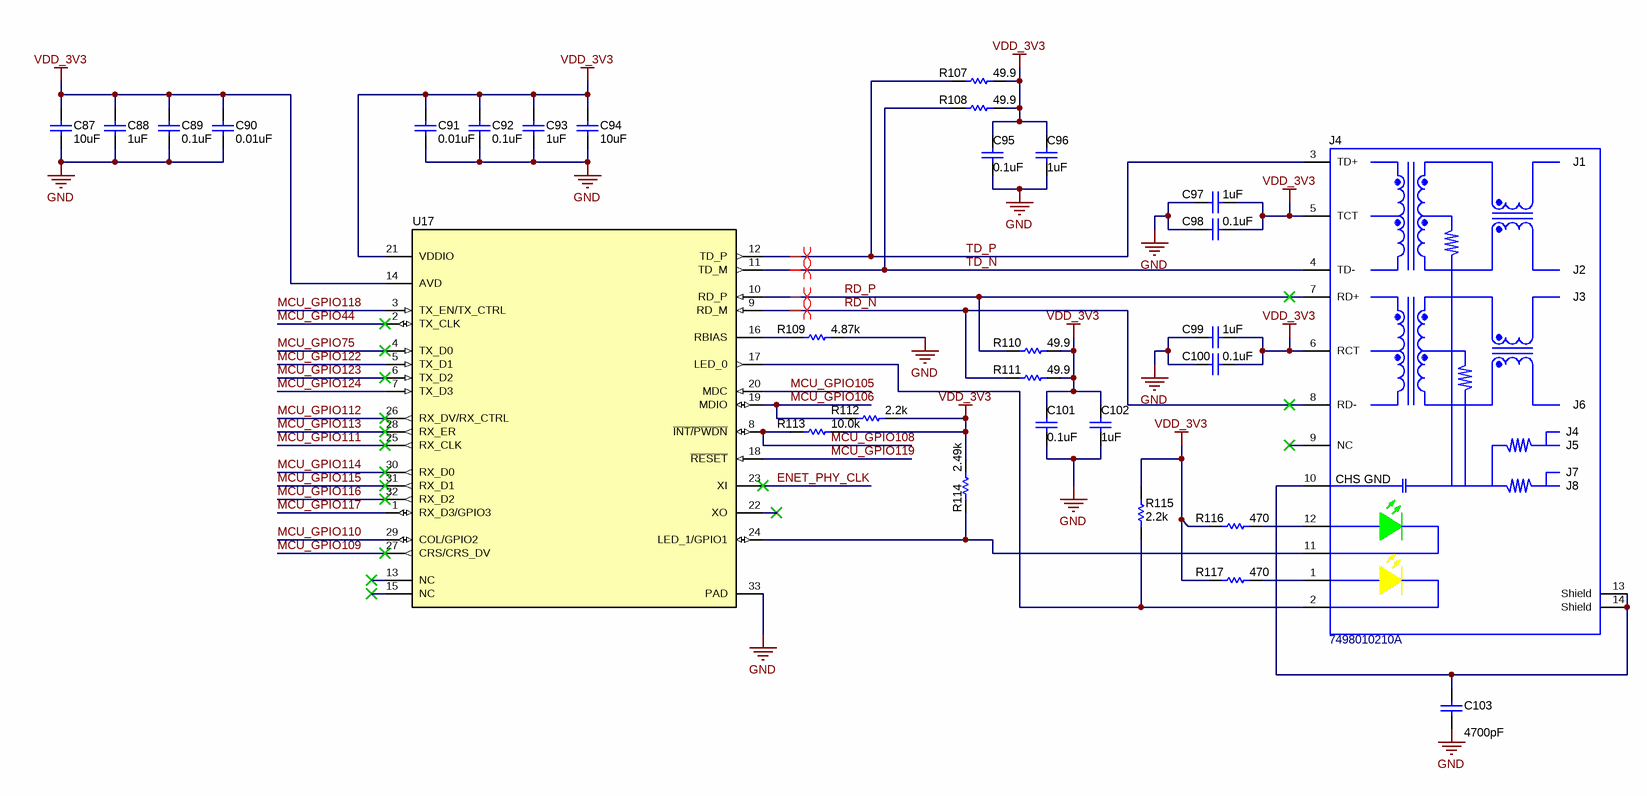
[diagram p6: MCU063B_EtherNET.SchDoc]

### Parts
C87  ValueDisplayed: 10uF  [0402]  (hidden comment: CL05A106MQ5NUNC)
C88  ValueDisplayed: 1uF  [0402]  (hidden comment: EMK105BJ105KVHF)
C89  ValueDisplayed: 0.1uF  [0402]  (hidden comment: LMK105BJ104KV-F)
C90  ValueDisplayed: 0.01uF  [0402]  (hidden comment: 885012205031)
C91  ValueDisplayed: 0.01uF  [0402]  (hidden comment: 885012205031)
C92  ValueDisplayed: 0.1uF  [0402]  (hidden comment: LMK105BJ104KV-F)
C93  ValueDisplayed: 1uF  [0402]  (hidden comment: EMK105BJ105KVHF)
C94  ValueDisplayed: 10uF  [0402]  (hidden comment: CL05A106MQ5NUNC)
C95  ValueDisplayed: 0.1uF  [0402]  (hidden comment: LMK105BJ104KV-F)
C96  ValueDisplayed: 1uF  [0402]  (hidden comment: EMK105BJ105KVHF)
C97  ValueDisplayed: 1uF  [0402]  (hidden comment: EMK105BJ105KVHF)
C98  ValueDisplayed: 0.1uF  [0402]  (hidden comment: LMK105BJ104KV-F)
C99  ValueDisplayed: 1uF  [0402]  (hidden comment: EMK105BJ105KVHF)
C100  ValueDisplayed: 0.1uF  [0402]  (hidden comment: LMK105BJ104KV-F)
C101  ValueDisplayed: 0.1uF  [0402]  (hidden comment: LMK105BJ104KV-F)
C102  ValueDisplayed: 1uF  [0402]  (hidden comment: EMK105BJ105KVHF)
C103  ValueDisplayed: 4700pF  [1206]  (hidden comment: 12061C472KAT2A)
J4  7498010210A  [Wurth_7498010210A]
R107  ValueDisplayed: 49.9  [0402]  (hidden comment: RC0402FR-0749R9L)
R108  ValueDisplayed: 49.9  [0402]  (hidden comment: RC0402FR-0749R9L)
R109  ValueDisplayed: 4.87k  [0402]  (hidden comment: CRCW04024K87FKED)
R110  ValueDisplayed: 49.9  [0402]  (hidden comment: RC0402FR-0749R9L)
R111  ValueDisplayed: 49.9  [0402]  (hidden comment: RC0402FR-0749R9L)
R112  ValueDisplayed: 2.2k  [0402]  (hidden comment: CRCW04022K20JNED)
R113  ValueDisplayed: 10.0k  [0402]  (hidden comment: RC0402FR-0710KL)
R114  ValueDisplayed: 2.49k  [0402]  (hidden comment: CRCW04022K49FKED)
R115  ValueDisplayed: 2.2k  [0402]  (hidden comment: CRCW04022K20JNED)
R116  ValueDisplayed: 470  [0603]  (hidden comment: CRCW0603470RJNEA)
R117  ValueDisplayed: 470  [0603]  (hidden comment: CRCW0603470RJNEA)
U17  DP83822IRHBR  [RHB0032B]  (value not drawn)

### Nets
GND: C87.2 C88.2 C89.2 C90.2 C91.2 C92.2 C93.2 C94.2 C95.2 C96.2 C97.1 C98.1 C99.1 C100.1 C101.2 C102.2 C103.1 R109.2 U17.33(PAD)
VDD_3V3: C87.1 C88.1 C89.1 C90.1 C91.1 C92.1 C93.1 C94.1 C95.1 C96.1 C97.2 C98.2 C99.2 C100.2 C101.1 C102.1 J4.5(TCT) J4.6(RCT) R107.2 R108.2 R110.2 R111.2 R112.1 R113.2 R114.2 R115.2 R116.1 R117.1 U17.14(AVD) U17.21(VDDIO)
ENET_PHY_CLK: U17.23(XI)
MCU_GPIO44: U17.2(TX_CLK)
MCU_GPIO75: U17.4(TX_D0)
MCU_GPIO105: U17.20(MDC)
MCU_GPIO106: R112.2 U17.19(MDIO)
MCU_GPIO108: R113.1 U17.8(~{INT/PWDN})
MCU_GPIO109: U17.27(CRS/CRS_DV)
MCU_GPIO110: U17.29(COL/GPIO2)
MCU_GPIO111: U17.25(RX_CLK)
MCU_GPIO112: U17.26(RX_DV/RX_CTRL)
MCU_GPIO113: U17.28(RX_ER)
MCU_GPIO114: U17.30(RX_D0)
MCU_GPIO115: U17.31(RX_D1)
MCU_GPIO116: U17.32(RX_D2)
MCU_GPIO117: U17.1(RX_D3/GPIO3)
MCU_GPIO118: U17.3(TX_EN/TX_CTRL)
MCU_GPIO119: U17.18(~{RESET})
MCU_GPIO122: U17.5(TX_D1)
MCU_GPIO123: U17.6(TX_D2)
MCU_GPIO124: U17.7(TX_D3)
RD_N: J4.8(RD-) R111.1 U17.9(RD_M)
RD_P: J4.7(RD+) R110.1 U17.10(RD_P)
TD_N: J4.4(TD-) R108.1 U17.11(TD_M)
TD_P: J4.3(TD+) R107.1 U17.12(TD_P)
NetC103_2: C103.2 J4.10(CHS_GND) J4.13(Shield) J4.14(Shield)
NetJ4_1: J4.1(RIGHT_LED_ANODE) R117.2
NetJ4_2: J4.2(RIGHT_LED_CATHODE) R115.1 U17.17(LED_0)
NetJ4_11: J4.11(LEFT_LED_CATHODE) R114.1 U17.24(LED_1/GPIO1)
NetJ4_12: J4.12(LEFT_LED_ANODE) R116.2
NetR109_1: R109.1 U17.16(RBIAS)

Not connected (* = marked no-connect by the designer): J4 9(NC)*; U17 13(NC)* 15(NC)* 22(XO)*

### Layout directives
differential pair: RD_N, RD_P, TD_N, TD_P

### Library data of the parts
C87 C94 = CMP-0006340-2: CAP, CERM, 10 uF, 6.3 V, +/- 20%, X5R, 0402; Manufacturer: Samsung Electro-Mechanics; TaMin_C: -55°C; Polarized: N; SizeAreaWB_mm2: 3; Value1: Unknown; U/M: EA; Value: 10uF; TaMax_C: 85°C; SizeZ_mm: 0.6; SizeX_mm: 1; SizeY_mm: 0.5; Value2: 6.3V; Cap_F: 10µF; AEC Category: Q200
C88 C93 C96 C97 C99 C102 = CMP-0006347-2: CAP, CERM, 1 uF, 16 V, +/- 10%, X5R, 0402; Manufacturer: Taiyo Yuden; TaMin_C: -55°C; Polarized: N; SizeAreaWB_mm2: 3; Value1: Unknown; U/M: EA; Value: 1uF; TaMax_C: 85°C; SizeZ_mm: 0.6; SizeX_mm: 1; SizeY_mm: 0.5; Value2: 16V; Cap_F: 1µF; AEC Category: Q200
C89 C92 C95 C98 C100 C101 = CMP-0064930-2: CAP, CERM, 0.1 uF, 10 V,+/- 10%, X5R, 0402; Manufacturer: Taiyo Yuden; TaMin_C: -55°C; Polarized: N; SizeAreaWB_mm2: 3; Value1: Unknown; U/M: EA; Value: 0.1uF; TaMax_C: 85°C; SizeZ_mm: 0.6; SizeX_mm: 1; SizeY_mm: 0.5; Value2: 10V; Cap_F: 100nF; AEC Category: Q200
C90 C91 = CMP-0006227-2: CAP, CERM, 0.01 uF, 16 V, +/- 10%, X7R, 0402; Manufacturer: Wurth Elektronik; TaMin_C: -55°C; Polarized: N; SizeAreaWB_mm2: 3; Value1: Unknown; U/M: EA; Value: 0.01uF; TaMax_C: 125°C; SizeZ_mm: 0.6; SizeX_mm: 1; SizeY_mm: 0.5; Value2: 16V; Cap_F: 10nF; AEC Category: Q200
C103 = CMP-0008501-2: CAP, CERM, 4700 pF, 100 V, +/- 10%, X7R, 1206; Manufacturer: AVX; TaMin_C: -55°C; ESR_ohm: 1.78d; Polarized: N; SizeAreaWB_mm2: 10.92; Value1: 0.178 ohm; U/M: EA; Value: 4700pF; TaMax_C: 125°C; SizeZ_mm: 1.35; SizeX_mm: 3.2; SizeY_mm: 1.6; Value2: 100V; SizeArea_mm2: 5.12; Cap_F: 4.7nF; AEC Category: Q200
J4 = CMP-0086350-1: Connector, RJ45, 1x1, Gold, R/A, SMT; Manufacturer: Wurth Elektronik; Row_Count: 1; Gender: Female
R107 R108 R110 R111 = CMP-0026738-1: RES, 49.9, 1%, 0.063 W, 0402; Manufacturer: Yageo America; Power_W: 63mW; TempCo: 100 ppm/C; Value_Code: 49R9; U/M: EA; Value: 49.9; EIA_Code: E96; SizeX_mm: 1; SizeY_mm: 0.5; SizeZ_mm: 0.6; Value2: 0.063W; AEC Qualified: N; VDC_V: 50V; AEC Category: Q200
R109 = CMP-0026413-2: RES, 4.87 k, 1%, 0.063 W, AEC-Q200 Grade 0, 0402; Manufacturer: Vishay-Dale; Power_W: 63mW; TempCo: 100 ppm/C; Value_Code: 4k87; Value: 4.87k; EIA_Code: E96; SizeX_mm: 1; SizeY_mm: 0.5; SizeZ_mm: 0.6; Value2: 0.063W; AEC Qualified: Y; VDC_V: 50V; AEC Category: Q200; AEC Grade: 0
R112 R115 = CMP-0026890-5: RES, 2.2 k, 5%, 0.063 W, AEC-Q200 Grade 0, 0402; Manufacturer: Vishay-Dale; Power_W: 63mW; TempCo: 200 ppm/C; Value_Code: 2k20; Value: 2.2k; EIA_Code: E24; SizeX_mm: 1; SizeY_mm: 0.5; SizeZ_mm: 0.6; Value2: 0.063W; AEC Qualified: Y; VDC_V: 50V; AEC Category: Q200; AEC Grade: 0
R113 = CMP-0078669-1: RES, 10.0 k, 1%, 0.063 W, 0402; Manufacturer: Yageo America; Power_W: 63mW; Green_Lifecycle: Active; TempCo: 100 ppm/C; Value_Code: 10k0; Green_REACh: Passed; Value: 10.0k; EIA_Code: E96; Res_ohm: 10k; SizeX_mm: 1; SizeY_mm: 0.5; SizeZ_mm: 0.6; Value2: 0.063W; AEC Qualified: N; AEC Category: Q200
R114 = CMP-0026237-2: RES, 2.49 k, 1%, 0.063 W, AEC-Q200 Grade 0, 0402; Manufacturer: Vishay-Dale; Power_W: 63mW; TempCo: 100 ppm/C; Value_Code: 2k49; Value: 2.49k; EIA_Code: E96; SizeX_mm: 1; SizeY_mm: 0.5; SizeZ_mm: 0.6; Value2: 0.063W; AEC Qualified: Y; VDC_V: 50V; AEC Category: Q200; AEC Grade: 0
R116 R117 = CMP-0025813-4: RES, 470, 5%, 0.1 W, AEC-Q200 Grade 0, 0603; Manufacturer: Vishay-Dale; Power_W: 100mW; TempCo: 200 ppm/C; Value_Code: 470R; Value: 470; EIA_Code: E24; SizeX_mm: 1.6; SizeY_mm: 0.8; SizeZ_mm: 1; Value2: 0.1W; SizeArea_mm2: 1.28; AEC Qualified: Y; VDC_V: 75V; AEC Category: Q200; AEC Grade: 0
U17 = CMP-0076010-4: Robust, Low Power 10/100 Ethernet Physical Layer Transceiver, RHB0032B (VQFN-32); Alternate PartNumber: DP83822IRHBT; Manufacturer: Texas Instruments; SizeZ_mm: 1.0; SizeX_mm: 5.0; SizeArea_mm2: 25.0; CompType: IC; SizeAreaWB_mm2: 49.0; AEC Category: Q200; AEC Qualified: N

## Sheet MCU063B_EtherCAT.SchDoc
size 431 x 279 mm; Date: Not shown in title block; ApprovedBy: Not shown in title block; CheckedBy: Not shown in title block; Author: Not shown in title block; CompanyName: Not shown in title block; Engineer: Not shown in title block; Organization: Not shown in title block; Address1: Not shown in title block; Address2: Not shown in title block; Address3: Not shown in title block; Address4: Not shown in title block; DocumentNumber: 8; Revision: Use project parameter SCH_Rev; SheetNumber: 8; SheetTotal: 11; PageSetup: Record=PageOptions¦CenterHorizontal=True¦CenterVertical=True¦PrintScale=1.00¦XCorrection=1.00¦YCorrection=1.00¦PrintKind=0¦BorderSize=5000000¦LeftOffset=0¦BottomOffset=0¦Orientation=2¦PaperLength=1000¦PaperWidth=1000¦Scale=100¦PaperSource=15¦PrintQuality=600¦MediaType=1¦DitherType=10¦PaperKind=Letter¦PrintScaleMode=1
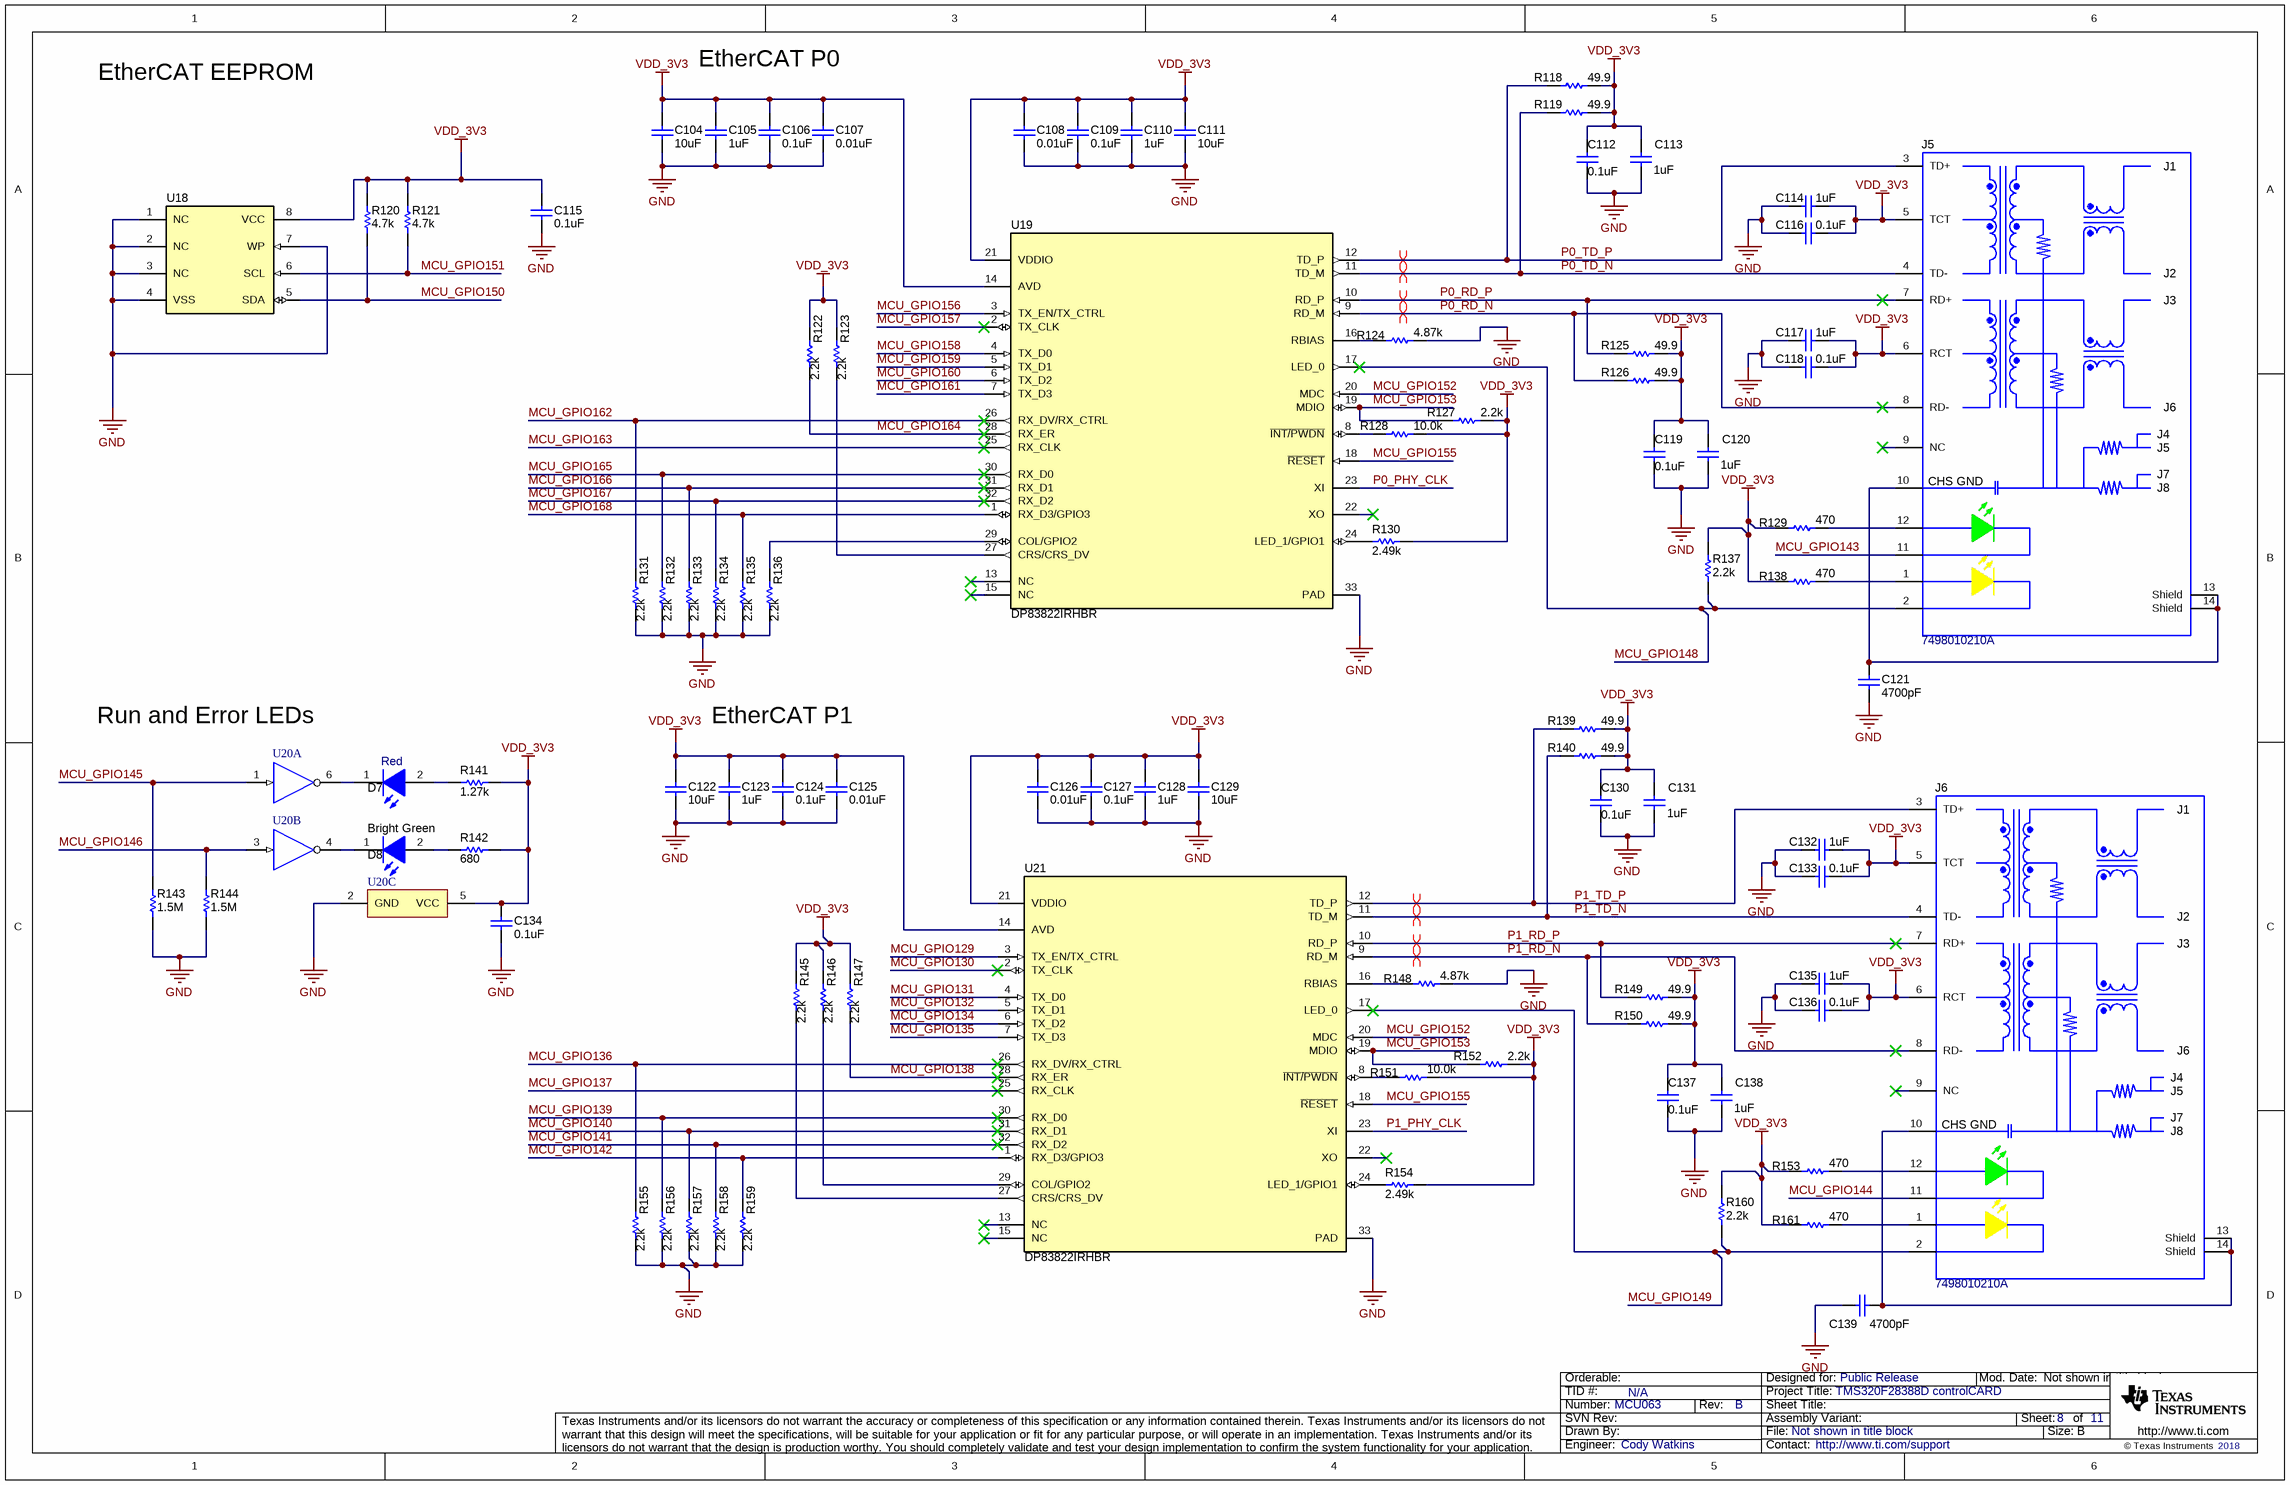
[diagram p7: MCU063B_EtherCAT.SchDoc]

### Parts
C104  ValueDisplayed: 10uF  [0402]  (hidden comment: CL05A106MQ5NUNC)
C105  ValueDisplayed: 1uF  [0402]  (hidden comment: EMK105BJ105KVHF)
C106  ValueDisplayed: 0.1uF  [0402]  (hidden comment: LMK105BJ104KV-F)
C107  ValueDisplayed: 0.01uF  [0402]  (hidden comment: 885012205031)
C108  ValueDisplayed: 0.01uF  [0402]  (hidden comment: 885012205031)
C109  ValueDisplayed: 0.1uF  [0402]  (hidden comment: LMK105BJ104KV-F)
C110  ValueDisplayed: 1uF  [0402]  (hidden comment: EMK105BJ105KVHF)
C111  ValueDisplayed: 10uF  [0402]  (hidden comment: CL05A106MQ5NUNC)
C112  ValueDisplayed: 0.1uF  [0402]  (hidden comment: LMK105BJ104KV-F)
C113  ValueDisplayed: 1uF  [0402]  (hidden comment: EMK105BJ105KVHF)
C114  ValueDisplayed: 1uF  [0402]  (hidden comment: EMK105BJ105KVHF)
C115  ValueDisplayed: 0.1uF  [0402]  (hidden comment: CL05B104KP5NNNC)
C116  ValueDisplayed: 0.1uF  [0402]  (hidden comment: LMK105BJ104KV-F)
C117  ValueDisplayed: 1uF  [0402]  (hidden comment: EMK105BJ105KVHF)
C118  ValueDisplayed: 0.1uF  [0402]  (hidden comment: LMK105BJ104KV-F)
C119  ValueDisplayed: 0.1uF  [0402]  (hidden comment: LMK105BJ104KV-F)
C120  ValueDisplayed: 1uF  [0402]  (hidden comment: EMK105BJ105KVHF)
C121  ValueDisplayed: 4700pF  [1206]  (hidden comment: 12061C472KAT2A)
C122  ValueDisplayed: 10uF  [0402]  (hidden comment: CL05A106MQ5NUNC)
C123  ValueDisplayed: 1uF  [0402]  (hidden comment: EMK105BJ105KVHF)
C124  ValueDisplayed: 0.1uF  [0402]  (hidden comment: LMK105BJ104KV-F)
C125  ValueDisplayed: 0.01uF  [0402]  (hidden comment: 885012205031)
C126  ValueDisplayed: 0.01uF  [0402]  (hidden comment: 885012205031)
C127  ValueDisplayed: 0.1uF  [0402]  (hidden comment: LMK105BJ104KV-F)
C128  ValueDisplayed: 1uF  [0402]  (hidden comment: EMK105BJ105KVHF)
C129  ValueDisplayed: 10uF  [0402]  (hidden comment: CL05A106MQ5NUNC)
C130  ValueDisplayed: 0.1uF  [0402]  (hidden comment: LMK105BJ104KV-F)
C131  ValueDisplayed: 1uF  [0402]  (hidden comment: EMK105BJ105KVHF)
C132  ValueDisplayed: 1uF  [0402]  (hidden comment: EMK105BJ105KVHF)
C133  ValueDisplayed: 0.1uF  [0402]  (hidden comment: LMK105BJ104KV-F)
C134  ValueDisplayed: 0.1uF  [0402]  (hidden comment: CL05B104KP5NNNC)
C135  ValueDisplayed: 1uF  [0402]  (hidden comment: EMK105BJ105KVHF)
C136  ValueDisplayed: 0.1uF  [0402]  (hidden comment: LMK105BJ104KV-F)
C137  ValueDisplayed: 0.1uF  [0402]  (hidden comment: LMK105BJ104KV-F)
C138  ValueDisplayed: 1uF  [0402]  (hidden comment: EMK105BJ105KVHF)
C139  ValueDisplayed: 4700pF  [1206]  (hidden comment: 12061C472KAT2A)
D7  value Red  [WL-SMCW_RED_0805]  (hidden comment: 150080SS75000)
D8  value Bright Green  [WL-SMCW_Green_0805]  (hidden comment: 150080VS75000)
J5  7498010210A  [Wurth_7498010210A]
J6  7498010210A  [Wurth_7498010210A]
R118  ValueDisplayed: 49.9  [0402]  (hidden comment: RC0402FR-0749R9L)
R119  ValueDisplayed: 49.9  [0402]  (hidden comment: RC0402FR-0749R9L)
R120  ValueDisplayed: 4.7k  [0402]  (hidden comment: CRCW04024K70JNED)
R121  ValueDisplayed: 4.7k  [0402]  (hidden comment: CRCW04024K70JNED)
R122  ValueDisplayed: 2.2k  [0201]  (hidden comment: CRCW02012K20JNED)
R123  ValueDisplayed: 2.2k  [0201]  (hidden comment: CRCW02012K20JNED)
R124  ValueDisplayed: 4.87k  [0402]  (hidden comment: CRCW04024K87FKED)
R125  ValueDisplayed: 49.9  [0402]  (hidden comment: RC0402FR-0749R9L)
R126  ValueDisplayed: 49.9  [0402]  (hidden comment: RC0402FR-0749R9L)
R127  ValueDisplayed: 2.2k  [0402]  (hidden comment: CRCW04022K20JNED)
R128  ValueDisplayed: 10.0k  [0402]  (hidden comment: RC0402FR-0710KL)
R129  ValueDisplayed: 470  [0603]  (hidden comment: CRCW0603470RJNEA)
R130  ValueDisplayed: 2.49k  [0402]  (hidden comment: CRCW04022K49FKED)
R131  ValueDisplayed: 2.2k  [0201]  (hidden comment: CRCW02012K20JNED)
R132  ValueDisplayed: 2.2k  [0201]  (hidden comment: CRCW02012K20JNED)
R133  ValueDisplayed: 2.2k  [0201]  (hidden comment: CRCW02012K20JNED)
R134  ValueDisplayed: 2.2k  [0201]  (hidden comment: CRCW02012K20JNED)
R135  ValueDisplayed: 2.2k  [0201]  (hidden comment: CRCW02012K20JNED)
R136  ValueDisplayed: 2.2k  [0201]  (hidden comment: CRCW02012K20JNED)
R137  ValueDisplayed: 2.2k  [0402]  (hidden comment: CRCW04022K20JNED)
R138  ValueDisplayed: 470  [0603]  (hidden comment: CRCW0603470RJNEA)
R139  ValueDisplayed: 49.9  [0402]  (hidden comment: RC0402FR-0749R9L)
R140  ValueDisplayed: 49.9  [0402]  (hidden comment: RC0402FR-0749R9L)
R141  ValueDisplayed: 1.27k  [0402]  (hidden comment: CRCW04021K27FKED)
R142  ValueDisplayed: 680  [0402]  (hidden comment: CRCW0402680RJNED)
R143  ValueDisplayed: 1.5M  [0402]  (hidden comment: CRCW04021M50JNED)
R144  ValueDisplayed: 1.5M  [0402]  (hidden comment: CRCW04021M50JNED)
R145  ValueDisplayed: 2.2k  [0201]  (hidden comment: CRCW02012K20JNED)
R146  ValueDisplayed: 2.2k  [0201]  (hidden comment: CRCW02012K20JNED)
R147  ValueDisplayed: 2.2k  [0201]  (hidden comment: CRCW02012K20JNED)
R148  ValueDisplayed: 4.87k  [0402]  (hidden comment: CRCW04024K87FKED)
R149  ValueDisplayed: 49.9  [0402]  (hidden comment: RC0402FR-0749R9L)
R150  ValueDisplayed: 49.9  [0402]  (hidden comment: RC0402FR-0749R9L)
R151  ValueDisplayed: 10.0k  [0402]  (hidden comment: RC0402FR-0710KL)
R152  ValueDisplayed: 2.2k  [0402]  (hidden comment: CRCW04022K20JNED)
R153  ValueDisplayed: 470  [0603]  (hidden comment: CRCW0603470RJNEA)
R154  ValueDisplayed: 2.49k  [0402]  (hidden comment: CRCW04022K49FKED)
R155  ValueDisplayed: 2.2k  [0201]  (hidden comment: CRCW02012K20JNED)
R156  ValueDisplayed: 2.2k  [0201]  (hidden comment: CRCW02012K20JNED)
R157  ValueDisplayed: 2.2k  [0201]  (hidden comment: CRCW02012K20JNED)
R158  ValueDisplayed: 2.2k  [0201]  (hidden comment: CRCW02012K20JNED)
R159  ValueDisplayed: 2.2k  [0201]  (hidden comment: CRCW02012K20JNED)
R160  ValueDisplayed: 2.2k  [0402]  (hidden comment: CRCW04022K20JNED)
R161  ValueDisplayed: 470  [0603]  (hidden comment: CRCW0603470RJNEA)
U18  CAT24C16WI-GT3  [SOIC-8]  (value not drawn)
U19  DP83822IRHBR  [RHB0032B]
U20  SN74LVC2G06DBVR  [DBV0006A_N]  (value not drawn)  (parts A,B,C of 3)
U21  DP83822IRHBR  [RHB0032B]

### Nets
GND: C104.2 C105.2 C106.2 C107.2 C108.2 C109.2 C110.2 C111.2 C112.2 C113.2 C114.1 C115.2 C116.1 C117.1 C118.1 C119.2 C120.2 C121.1 C122.2 C123.2 C124.2 C125.2 C126.2 C127.2 C128.2 C129.2 C130.2 C131.2 C132.1 C133.1 C134.2 C135.1 C136.1 C137.2 C138.2 C139.1 R124.2 R131.1 R132.1 R133.1 R134.1 R135.1 R136.1 R143.2 R144.2 R148.2 R155.1 R156.1 R157.1 R158.1 R159.1 U18.1(NC) U18.2(NC) U18.3(NC) U18.4(VSS) U18.7(WP) U19.33(PAD) U20.2(GND) U21.33(PAD)
VDD_3V3: C104.1 C105.1 C106.1 C107.1 C108.1 C109.1 C110.1 C111.1 C112.1 C113.1 C114.2 C115.1 C116.2 C117.2 C118.2 C119.1 C120.1 C122.1 C123.1 C124.1 C125.1 C126.1 C127.1 C128.1 C129.1 C130.1 C131.1 C132.2 C133.2 C134.1 C135.2 C136.2 C137.1 C138.1 J5.5(TCT) J5.6(RCT) J6.5(TCT) J6.6(RCT) R118.2 R119.2 R120.2 R121.2 R122.2 R123.2 R125.2 R126.2 R127.1 R128.2 R129.1 R130.1 R137.2 R138.1 R139.2 R140.2 R141.2 R142.1 R145.2 R146.2 R147.2 R149.2 R150.2 R151.2 R152.1 R153.1 R154.1 R160.2 R161.1 U18.8(VCC) U19.14(AVD) U19.21(VDDIO) U20.5(VCC) U21.14(AVD) U21.21(VDDIO)
MCU_GPIO129: U21.3(TX_EN/TX_CTRL)
MCU_GPIO130: U21.2(TX_CLK)
MCU_GPIO131: U21.4(TX_D0)
MCU_GPIO132: U21.5(TX_D1)
MCU_GPIO134: U21.6(TX_D2)
MCU_GPIO135: U21.7(TX_D3)
MCU_GPIO136: R155.2 U21.26(RX_DV/RX_CTRL)
MCU_GPIO137: U21.25(RX_CLK)
MCU_GPIO138: R147.1 U21.28(RX_ER)
MCU_GPIO139: R156.2 U21.30(RX_D0)
MCU_GPIO140: R157.2 U21.31(RX_D1)
MCU_GPIO141: R158.2 U21.32(RX_D2)
MCU_GPIO142: R159.2 U21.1(RX_D3/GPIO3)
MCU_GPIO143: J5.11(LEFT_LED_CATHODE)
MCU_GPIO144: J6.11(LEFT_LED_CATHODE)
MCU_GPIO145: R143.1 U20.1(1A)
MCU_GPIO146: R144.1 U20.3(2A)
MCU_GPIO148: J5.2(RIGHT_LED_CATHODE) R137.1 U19.17(LED_0)
MCU_GPIO149: J6.2(RIGHT_LED_CATHODE) R160.1 U21.17(LED_0)
MCU_GPIO150: R120.1 U18.5(SDA)
MCU_GPIO151: R121.1 U18.6(SCL)
MCU_GPIO152: U19.20(MDC) U21.20(MDC)
MCU_GPIO153: R127.2 R152.2 U19.19(MDIO) U21.19(MDIO)
MCU_GPIO155: U19.18(~{RESET}) U21.18(~{RESET})
MCU_GPIO156: U19.3(TX_EN/TX_CTRL)
MCU_GPIO157: U19.2(TX_CLK)
MCU_GPIO158: U19.4(TX_D0)
MCU_GPIO159: U19.5(TX_D1)
MCU_GPIO160: U19.6(TX_D2)
MCU_GPIO161: U19.7(TX_D3)
MCU_GPIO162: R131.2 U19.26(RX_DV/RX_CTRL)
MCU_GPIO163: U19.25(RX_CLK)
MCU_GPIO164: R122.1 U19.28(RX_ER)
MCU_GPIO165: R132.2 U19.30(RX_D0)
MCU_GPIO166: R133.2 U19.31(RX_D1)
MCU_GPIO167: R134.2 U19.32(RX_D2)
MCU_GPIO168: R135.2 U19.1(RX_D3/GPIO3)
P0_PHY_CLK: U19.23(XI)
P0_RD_N: J5.8(RD-) R126.1 U19.9(RD_M)
P0_RD_P: J5.7(RD+) R125.1 U19.10(RD_P)
P0_TD_N: J5.4(TD-) R119.1 U19.11(TD_M)
P0_TD_P: J5.3(TD+) R118.1 U19.12(TD_P)
P1_PHY_CLK: U21.23(XI)
P1_RD_N: J6.8(RD-) R150.1 U21.9(RD_M)
P1_RD_P: J6.7(RD+) R149.1 U21.10(RD_P)
P1_TD_N: J6.4(TD-) R140.1 U21.11(TD_M)
P1_TD_P: J6.3(TD+) R139.1 U21.12(TD_P)
NetC121_2: C121.2 J5.10(CHS_GND) J5.13(Shield) J5.14(Shield)
NetC139_2: C139.2 J6.10(CHS_GND) J6.13(Shield) J6.14(Shield)
NetD7_1: D7.1(K) U20.6(1Y)
NetD7_2: D7.2(A) R141.1
NetD8_1: D8.1(K) U20.4(2Y)
NetD8_2: D8.2(A) R142.2
NetJ5_1: J5.1(RIGHT_LED_ANODE) R138.2
NetJ5_12: J5.12(LEFT_LED_ANODE) R129.2
NetJ6_1: J6.1(RIGHT_LED_ANODE) R161.2
NetJ6_12: J6.12(LEFT_LED_ANODE) R153.2
NetR123_1: R123.1 U19.27(CRS/CRS_DV)
NetR124_1: R124.1 U19.16(RBIAS)
NetR128_1: R128.1 U19.8(~{INT/PWDN})
NetR130_2: R130.2 U19.24(LED_1/GPIO1)
NetR136_2: R136.2 U19.29(COL/GPIO2)
NetR145_1: R145.1 U21.27(CRS/CRS_DV)
NetR146_1: R146.1 U21.29(COL/GPIO2)
NetR148_1: R148.1 U21.16(RBIAS)
NetR151_1: R151.1 U21.8(~{INT/PWDN})
NetR154_2: R154.2 U21.24(LED_1/GPIO1)

Not connected (* = marked no-connect by the designer): J5 9(NC)*; J6 9(NC)*; U19 13(NC)* 15(NC)* 22(XO)*; U21 13(NC)* 15(NC)* 22(XO)*

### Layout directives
differential pair: P0_RD_N, P0_RD_P, P0_TD_N, P0_TD_P, P1_RD_N, P1_RD_P, P1_TD_N, P1_TD_P

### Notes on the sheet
- EtherCAT EEPROM
- EtherCAT P0
- Run and Error LEDs
- EtherCAT P1

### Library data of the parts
C104 C111 C122 C129 = CMP-0006340-2: as C87 on sheet MCU063B_EtherNET
C105 C110 C113 C114 C117 C120 C123 C128 C131 C132 C135 C138 = CMP-0006347-2: as C88 on sheet MCU063B_EtherNET
C106 C109 C112 C116 C118 C119 C124 C127 C130 C133 C136 C137 = CMP-0064930-2: as C89 on sheet MCU063B_EtherNET
C107 C108 C125 C126 = CMP-0006227-2: as C90 on sheet MCU063B_EtherNET
C115 C134 = CMP-0006343-2: CAP, CERM, 0.1 uF, 10 V, +/- 10%, X7R, 0402; Manufacturer: Samsung Electro-Mechanics; Polarized: N; Value: 0.1uF; U/M: EA; Cap_F: 100nF; Value1: Unknown; VDC_V: 10V; TaMin_C: -55°C; TaMax_C: 125°C; AEC Category: Q200; SizeArea_mm2: 0.5; SizeAreaWB_mm2: 3; SizeX_mm: 1; SizeZ_mm: 0.6
C121 C139 = CMP-0008501-2: as C103 on sheet MCU063B_EtherNET
D7 = CMP-0002951-3: LED, Red, SMD; Manufacturer: Wurth Elektronik; Type: AlInGaP; Vf_V: 1.9V; Io_A: 30mA; Vr_V: 5V; Ir_A: 25µA; Tjmax_C: 85°C; Power_TotalModule: 72mW; Value1: 0.072W; Angle: 140
D8 = CMP-0002960-2: as D5 on sheet MCU063B_Power
J5 J6 = CMP-0086350-1: as J4 on sheet MCU063B_EtherNET
R118 R119 R125 R126 R139 R140 R149 R150 = CMP-0026738-1: as R107 on sheet MCU063B_EtherNET
R120 R121 = CMP-0026938-5: RES, 4.7 k, 5%, 0.063 W, AEC-Q200 Grade 0, 0402; Manufacturer: Vishay-Dale; Power_W: 63mW; TempCo: 200 ppm/C; Value_Code: 4k70; Value: 4.7k; EIA_Code: E24; SizeX_mm: 1; SizeY_mm: 0.5; SizeZ_mm: 0.6; Value2: 0.063W; AEC Qualified: Y; VDC_V: 50V; AEC Category: Q200; AEC Grade: 0
R122 R123 R131-R136 R145-R147 R155-R159 = CMP-0027010-2: RES, 2.2 k, 5%, 0.05 W, 0201; Manufacturer: Vishay-Dale; Power_W: 50mW; TempCo: 200 ppm/C; Value_Code: 2k20; Value: 2.2k; EIA_Code: E24; SizeX_mm: 0.6; SizeY_mm: 0.3; SizeZ_mm: 0.26; Value2: 0.05W; SizeArea_mm2: 0.18; AEC Qualified: N; VDC_V: 30V; AEC Category: Q200
R124 R148 = CMP-0026413-2: as R109 on sheet MCU063B_EtherNET
R127 R137 R152 R160 = CMP-0026890-5: as R112 on sheet MCU063B_EtherNET
R128 R151 = CMP-0078669-1: as R113 on sheet MCU063B_EtherNET
R129 R138 R153 R161 = CMP-0025813-4: as R116 on sheet MCU063B_EtherNET
R130 R154 = CMP-0026237-2: as R114 on sheet MCU063B_EtherNET
R141 = CMP-0026081-3: RES, 1.27 k, 1%, 0.063 W, AEC-Q200 Grade 0, 0402; Manufacturer: Vishay-Dale; Power_W: 63mW; TempCo: 100 ppm/C; Value_Code: 1k27; Value: 1.27k; EIA_Code: E96; SizeX_mm: 1; SizeY_mm: 0.5; SizeZ_mm: 0.6; Value2: 0.063W; AEC Qualified: Y; VDC_V: 50V; AEC Category: Q200; AEC Grade: 0
R142 = CMP-0026962-3: RES, 680, 5%, 0.063 W, AEC-Q200 Grade 0, 0402; Manufacturer: Vishay-Dale; Value: 680; Value_Code: 680R; Power_W: 63mW; Value2: 0.063W; VDC_V: 50V; TempCo: 200 ppm/C; EIA_Code: E24; AEC Category: Q200; AEC Qualified: Y; AEC Grade: 0; SizeArea_mm2: 0.5; SizeX_mm: 1; SizeZ_mm: 0.6
R143 R144 = CMP-0026863-2: RES, 1.5 M, 5%, 0.063 W, AEC-Q200 Grade 0, 0402; Manufacturer: Vishay-Dale; Power_W: 63mW; TempCo: 200 ppm/C; Value_Code: 1M50; Value: 1.5Meg; EIA_Code: E24; SizeX_mm: 1; SizeY_mm: 0.5; SizeZ_mm: 0.6; Value2: 0.063W; AEC Qualified: Y; VDC_V: 50V; AEC Category: Q200; AEC Grade: 0
U18 = CMP-0082059-1: 16 Kb I2C EEPROM Serial, SOIC-8; Manufacturer: ON Semiconductor; SizeArea_mm2: 29.351; SizeAreaWB_mm2: 55.131; SizeY_mm: 4.9; SizeZ_mm: 1.75; SizeX_mm: 5.99
U19 U21 = CMP-0076010-4: as U17 on sheet MCU063B_EtherNET
U20 = CMP-0051777-2: Dual Inverter Buffer/Driver with Open-Drain Output, DBV0006A, LARGE T&R; Manufacturer: Texas Instruments; Schmitt Trigger: No; Logic: Inverting; F @ Nom Voltage(Max)(Mhz): 150; VCC(Max)(V): 5.5; Rating: Catalog; Sub-Family: Inverting Buffer/Driver; Technology Family: LVC; VCC(Min)(V): 1.65; Voltage(Nom)(V): 1.8,2.5,3.3,5; Output Drive (IOL/IOH)(Max)(mA): 32/-32; Output Type: CMOS; ICC @ Nom Voltage(Max)(mA): 0.01; Bits(#): 2; tpd @ Nom Voltage(Max)(ns): 8.2,4.4,3.9,3.4; Input Type: CMOS/TTL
